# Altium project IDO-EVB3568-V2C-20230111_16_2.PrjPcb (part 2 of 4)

## Sheet P07.SchDoc
size 594 x 420 mm
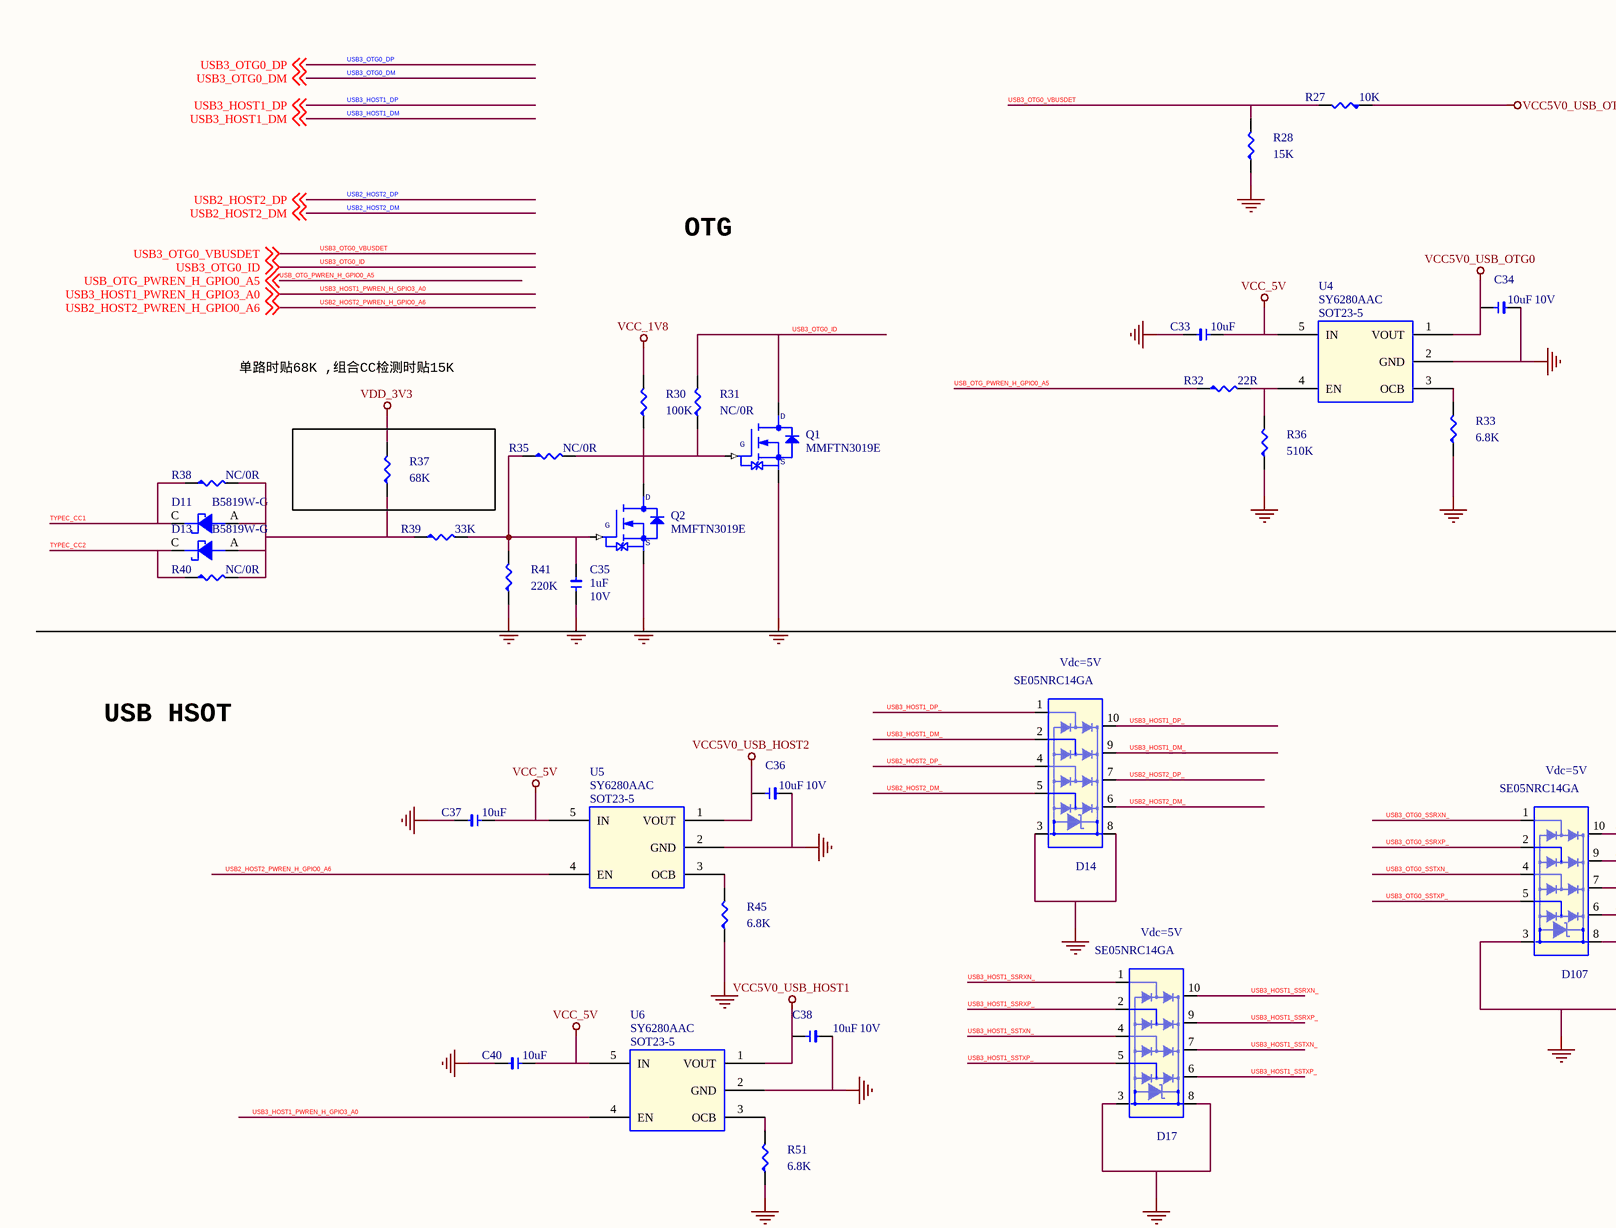
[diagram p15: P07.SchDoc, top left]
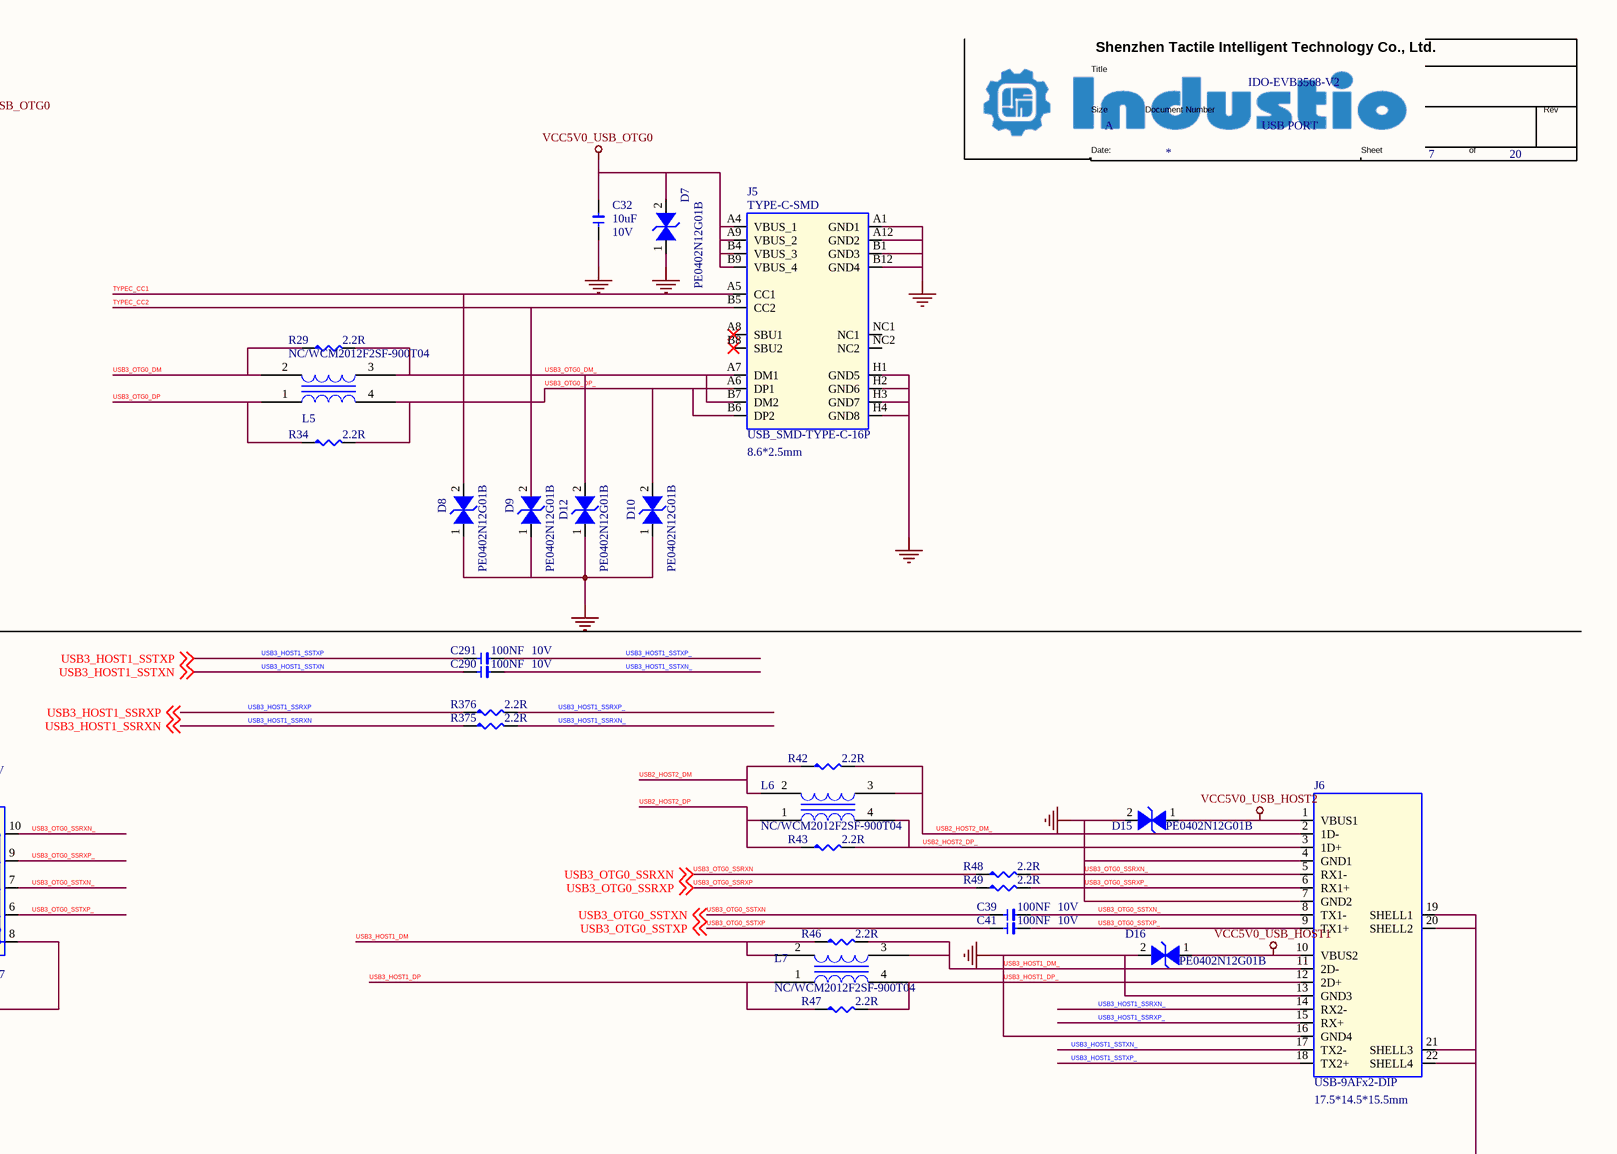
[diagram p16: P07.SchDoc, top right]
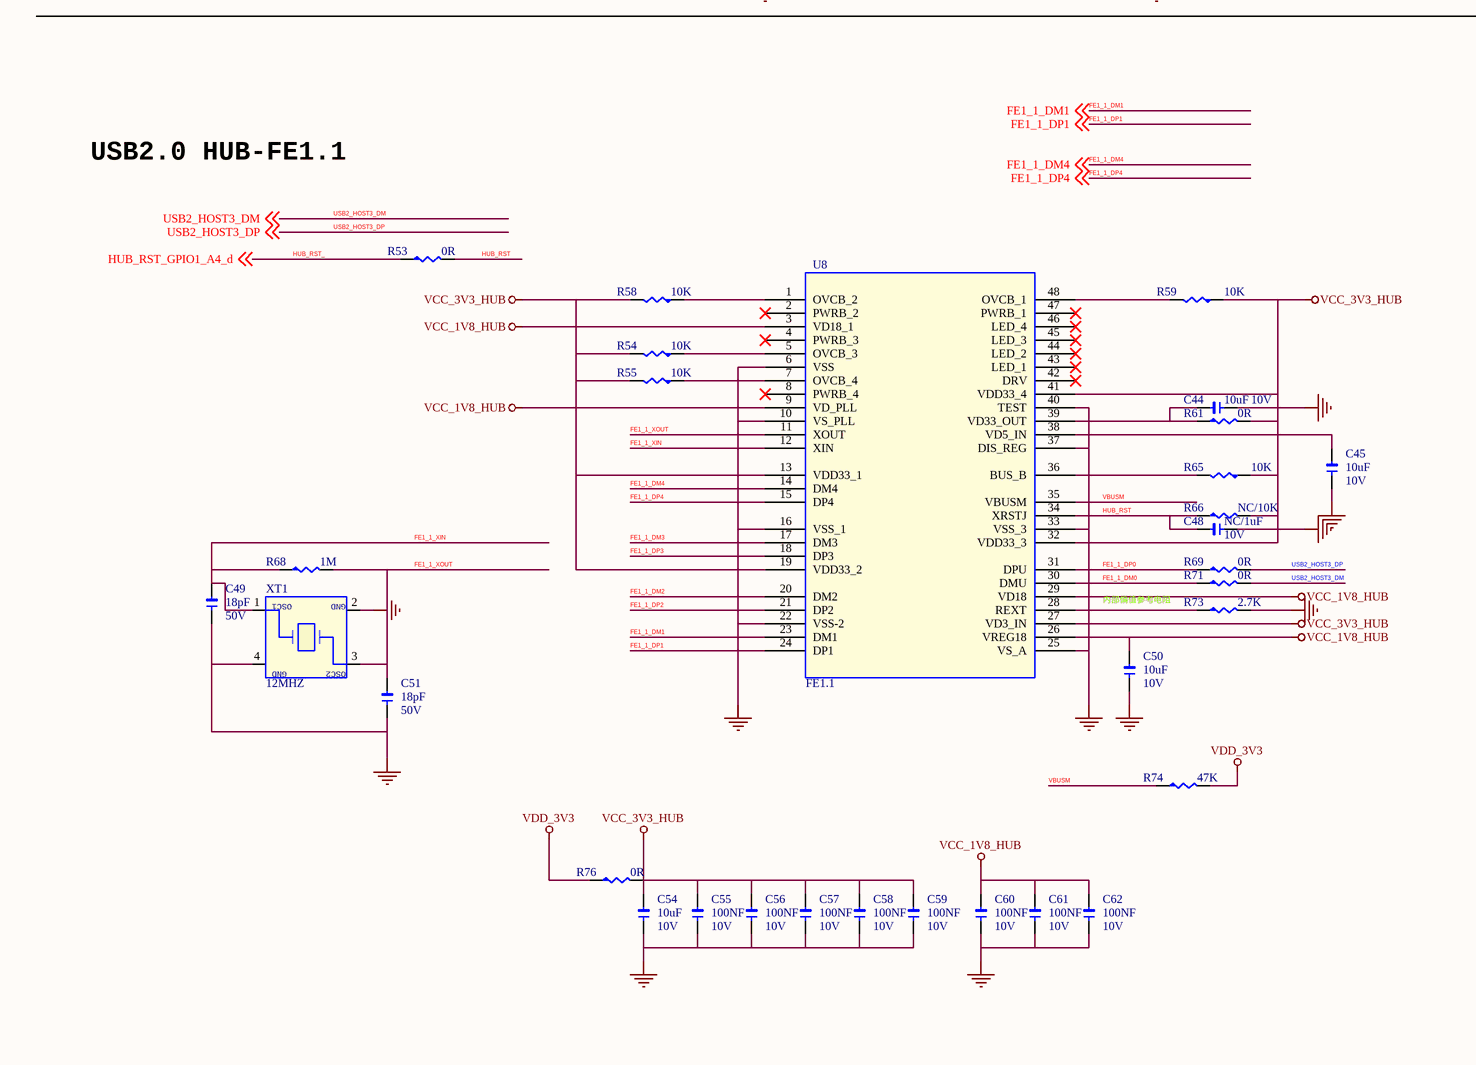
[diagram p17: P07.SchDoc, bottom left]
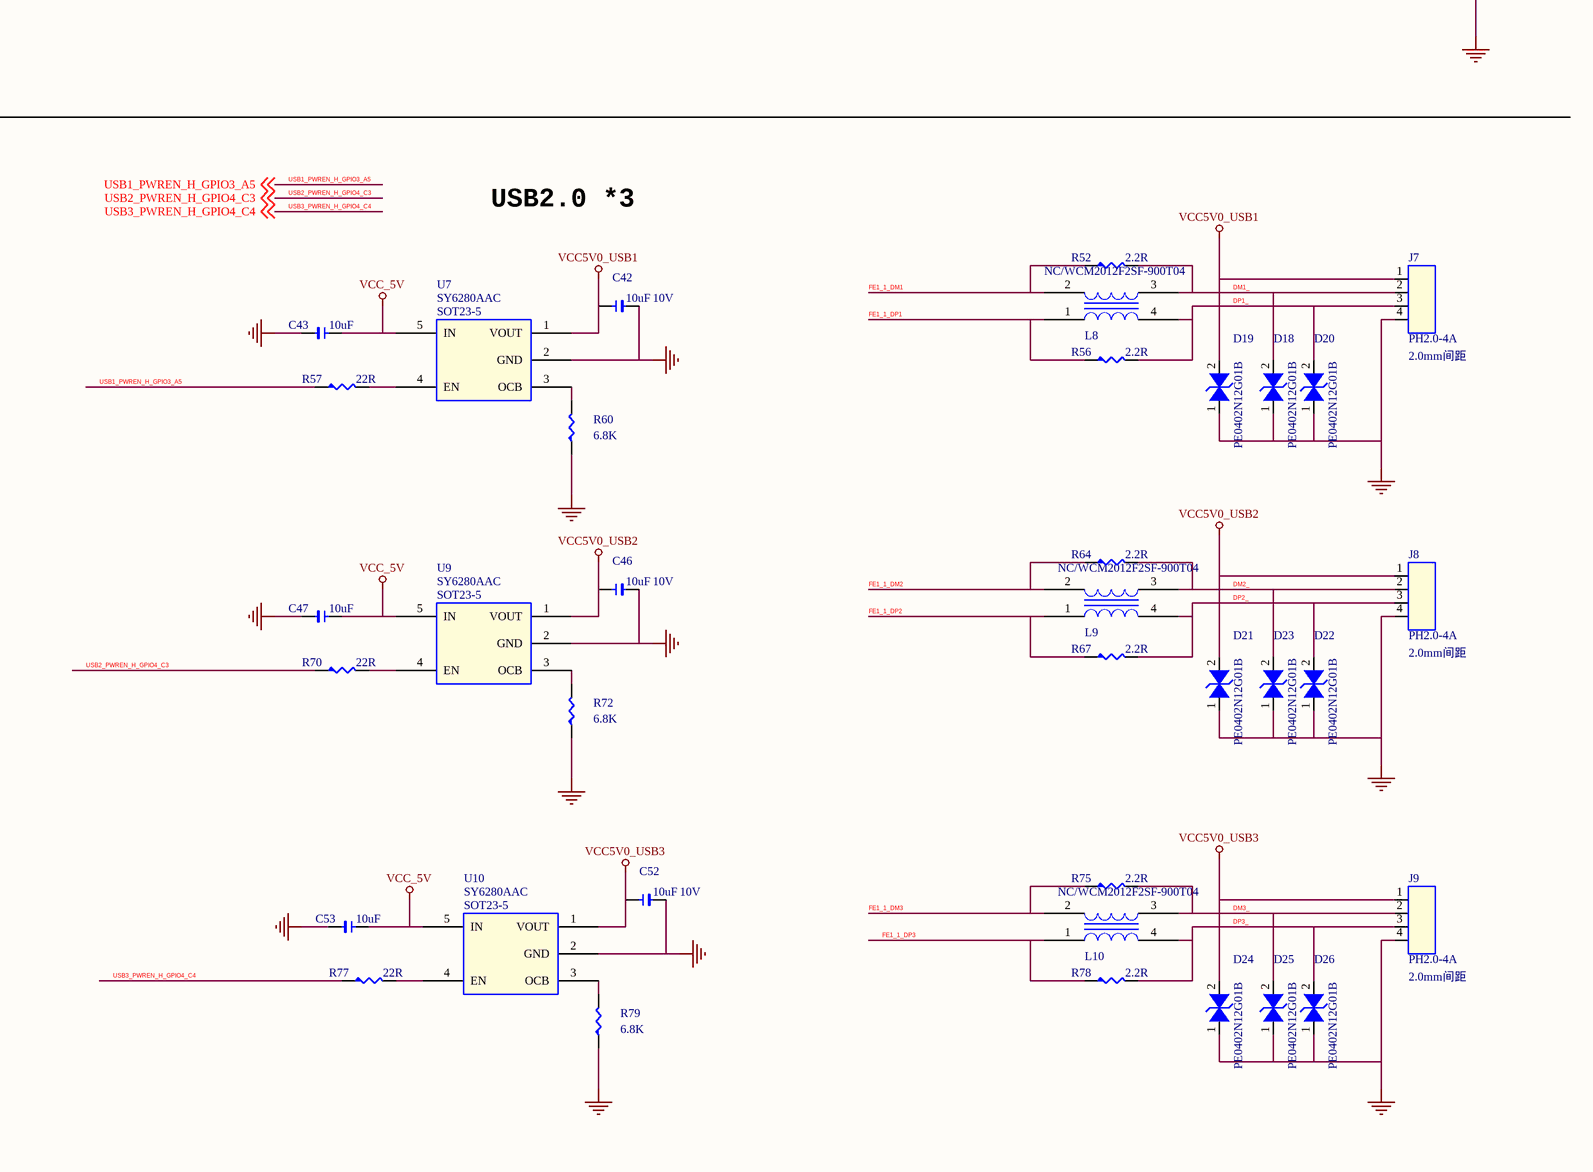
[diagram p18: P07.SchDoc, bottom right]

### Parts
(Parts that share a designator on the sheet are numbered #1, #2 ... from top to bottom, then left to right.)
*#6  Doc: USB PORT  Title: IDO-EVB3568-V2  Page Size: A  Page Number: 7  Page Count: 20  (hidden comment: TitleBlock1)  (graphical)
C32  10uF  DSC2: 10V  [1206]
C33  10uF  [1206]
C34  10uF  DSC2: 10V  [1206]
C35  1uF  DSC2: 10V  [1206]
C36  10uF  DSC2: 10V  [1206]
C37  10uF  [1206]
C38  10uF  DSC2: 10V  [1206]
C39  100NF  DSC2: 10V  [1206]
C40  10uF  [1206]
C41  100NF  DSC2: 10V  [1206]
C42  10uF  DSC2: 10V  [1206]
C43  10uF  [1206]
C44  10uF  DSC2: 10V  [1206]
C45  10uF  DSC2: 10V  [1206]
C46  10uF  DSC2: 10V  [1206]
C47  10uF  [1206]
C48  NC/1uF  DSC2: 10V  [1206]
C49  18pF  DSC2: 50V  [1206]
C50  10uF  DSC2: 10V  [1206]
C51  18pF  DSC2: 50V  [1206]
C52  10uF  DSC2: 10V  [1206]
C53  10uF  [1206]
C54  10uF  DSC2: 10V  [1206]
C55  100NF  DSC2: 10V  [1206]
C56  100NF  DSC2: 10V  [1206]
C57  100NF  DSC2: 10V  [1206]
C58  100NF  DSC2: 10V  [1206]
C59  100NF  DSC2: 10V  [1206]
C60  100NF  DSC2: 10V  [1206]
C61  100NF  DSC2: 10V  [1206]
C62  100NF  DSC2: 10V  [1206]
C290  100NF  DSC2: 10V  [1206]
C291  100NF  DSC2: 10V  [1206]
D7  PE0402N12G01B  [V0402]
D8  PE0402N12G01B  [V0402]
D9  PE0402N12G01B  [V0402]
D10  PE0402N12G01B  [V0402]
D11  B5819W-G  [SOD123]
D12  PE0402N12G01B  [V0402]
D13  B5819W-G  [SOD123]
D14  SE05NRC14GA  DSC2: Vdc=5V  [DFN2510-10L]
D15  PE0402N12G01B  [V0402]
D16  PE0402N12G01B  [V0402]
D17  SE05NRC14GA  DSC2: Vdc=5V  [DFN2510-10L]
D18  PE0402N12G01B  [V0402]
D19  PE0402N12G01B  [V0402]
D20  PE0402N12G01B  [V0402]
D21  PE0402N12G01B  [V0402]
D22  PE0402N12G01B  [V0402]
D23  PE0402N12G01B  [V0402]
D24  PE0402N12G01B  [V0402]
D25  PE0402N12G01B  [V0402]
D26  PE0402N12G01B  [V0402]
D107  SE05NRC14GA  DSC2: Vdc=5V  [DFN2510-10L]
J5  TYPE-C-SMD  DSC2: 8.6*2.5mm  [USB_SMD-TYPE-C-16P]
J6  USB-9AFx2-DIP  DSC2: 17.5*14.5*15.5mm  [USB-9AF-DIP_2x]
J7  PH2.0-4A  DSC2: 2.0mm间距  [PH200-4A]
J8  PH2.0-4A  DSC2: 2.0mm间距  [PH200-4A]
J9  PH2.0-4A  DSC2: 2.0mm间距  [PH200-4A]
L5  NC/WCM2012F2SF-900T04  [CMLS-ACM2012]
L6  NC/WCM2012F2SF-900T04  [CMLS-ACM2012]
L7  NC/WCM2012F2SF-900T04  [CMLS-ACM2012]
L8  NC/WCM2012F2SF-900T04  [CMLS-ACM2012]
L9  NC/WCM2012F2SF-900T04  [CMLS-ACM2012]
L10  NC/WCM2012F2SF-900T04  [CMLS-ACM2012]
Q1  MMFTN3019E  [SOT523]
Q2  MMFTN3019E  [SOT523]
R27  10K  [R0402]
R28  15K  [R0402]
R29  2.2R  [R0402]
R30  100K  [R0402]
R31  NC/0R  [R0402]
R32  22R  [R0402]
R33  6.8K  [R0402]
R34  2.2R  [R0402]
R35  NC/0R  [R0402]
R36  510K  [R0402]
R37  68K  [R0402]
R38  NC/0R  [R0402]
R39  33K  [R0402]
R40  NC/0R  [R0402]
R41  220K  [R0402]
R42  2.2R  [R0402]
R43  2.2R  [R0402]
R45  6.8K  [R0402]
R46  2.2R  [R0402]
R47  2.2R  [R0402]
R48  2.2R  [R0402]
R49  2.2R  [R0402]
R51  6.8K  [R0402]
R52  2.2R  [R0402]
R53  0R  [R0402]
R54  10K  [R0402]
R55  10K  [R0402]
R56  2.2R  [R0402]
R57  22R  [R0402]
R58  10K  [R0402]
R59  10K  [R0402]
R60  6.8K  [R0402]
R61  0R  [R0402]
R64  2.2R  [R0402]
R65  10K  [R0402]
R66  NC/10K  [R0402]
R67  2.2R  [R0402]
R68  1M  [R0402]
R69  0R  [R0402]
R70  22R  [R0402]
R71  0R  [R0402]
R72  6.8K  [R0402]
R73  2.7K  [R0402]
R74  47K  [R0402]
R75  2.2R  [R0402]
R76  0R  [R0402]
R77  22R  [R0402]
R78  2.2R  [R0402]
R79  6.8K  [R0402]
R375  2.2R  [R0402]
R376  2.2R  [R0402]
U4  SY6280AAC  [SOT23-5]
U5  SY6280AAC  [SOT23-5]
U6  SY6280AAC  [SOT23-5]
U7  SY6280AAC  [SOT23-5]
U8  FE1.1  [LQFP-48_7x7x05P]
U9  SY6280AAC  [SOT23-5]
U10  SY6280AAC  [SOT23-5]
XT1  12MHZ  [xtal_32x25_4p]

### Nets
GND: C32.1 C33.2 C34.2 C35.1 C36.2 C37.2 C38.2 C40.2 C42.2 C43.2 C44.1 C45.1 C46.2 C47.2 C48.1 C49.1 C50.1 C51.1 C52.2 C53.2 C54.1 C55.1 C56.1 C57.1 C58.1 C59.1 C60.1 C61.1 C62.1 D7.1(I/O2) D8.1(I/O2) D9.1(I/O2) D10.1(I/O2) D12.1(I/O2) D14.1 D14.2 D14.3 D14.8 D14.9 D14.10 D15.2(I/O1) D16.2(I/O1) D17.3 D17.8 D18.1(I/O2) D19.1(I/O2) D20.1(I/O2) D21.1(I/O2) D22.1(I/O2) D23.1(I/O2) D24.1(I/O2) D25.1(I/O2) D26.1(I/O2) D107.1 D107.2 D107.3 D107.8 D107.9 D107.10 J5.A1(GND1) J5.A12(GND2) J5.B1(GND3) J5.B12(GND4) J5.H1(GND5) J5.H2(GND6) J5.H3(GND7) J5.H4(GND8) J6.4(GND1) J6.5(RX1-) J6.6(RX1+) J6.7(GND2) J6.11(2D-) J6.12(2D+) J6.13(GND3) J6.16(GND4) J6.19(SHELL1) J6.20(SHELL2) J6.21(SHELL3) J6.22(SHELL4) J7.4 J8.4 J9.4 L7.3 L7.4 Q1.2(SOURCE) Q2.2(SOURCE) R28.1 R33.1 R36.1 R41.1 R45.1 R46.2 R47.2 R48.2 R49.2 R51.1 R60.1 R72.1 R73.2 R79.1 U4.2(GND) U5.2(GND) U6.2(GND) U7.2(GND) U8.6(VSS) U8.10(VS_PLL) U8.16(VSS_1) U8.22(VSS-2) U8.25(VS_A) U8.33(VSS_3) U8.37(DIS_REG) U8.40(TEST) U9.2(GND) U10.2(GND) XT1.2 XT1.4  [also labelled USB3_HOST1_DM_, USB3_HOST1_DP_, USB3_OTG0_SSRXN_, USB3_OTG0_SSRXP_]  [project net EDP_TX_AUXP_]
VCC5V0_USB1: C42.1 D19.2(I/O1) J7.1 U7.1(VOUT)
VCC5V0_USB2: C46.1 D21.2(I/O1) J8.1 U9.1(VOUT)
VCC5V0_USB3: C52.1 D24.2(I/O1) J9.1 U10.1(VOUT)
VCC5V0_USB_HOST1: C38.1 D16.1(I/O2) J6.10(VBUS2) U6.1(VOUT)
VCC5V0_USB_HOST2: C36.1 D15.1(I/O2) J6.1(VBUS1) U5.1(VOUT)
VCC5V0_USB_OTG0: C32.2 C34.1 D7.2(I/O1) J5.A4(VBUS_1) J5.A9(VBUS_2) J5.B4(VBUS_3) J5.B9(VBUS_4) R27.1 U4.1(VOUT)
VCC_1V8: R30.2
VCC_1V8_HUB: C50.2 C60.2 C61.2 C62.2 U8.3(VD18_1) U8.9(VD_PLL) U8.26(VREG18) U8.29(VD18)
VCC_3V3_HUB: C54.2 C55.2 C56.2 C57.2 C58.2 C59.2 R54.2 R55.2 R58.2 R59.1 R61.2 R65.1 R66.2 R76.2 U8.13(VDD33_1) U8.19(VDD33_2) U8.27(VD3_IN) U8.32(VDD33_3) U8.41(VDD33_4)
VCC_5V: C33.1 C37.1 C40.1 C43.1 C47.1 C53.1 U4.5(IN) U5.5(IN) U6.5(IN) U7.5(IN) U9.5(IN) U10.5(IN)
VDD_3V3: R37.2 R74.2 R76.1
DM1_: D18.2(I/O1) J7.2 L8.3 R52.2
DM2_: D23.2(I/O1) J8.2 L9.3 R64.2
DM3_: D25.2(I/O1) J9.2 L10.3 R75.2
DP1_: D20.2(I/O1) J7.3 L8.4 R56.2
DP2_: D22.2(I/O1) J8.3 L9.4 R67.2
DP3_: D26.2(I/O1) J9.3 L10.4 R78.2
FE1_1_DM0: R71.1 U8.30(DMU)
FE1_1_DM1: L8.2 R52.1 U8.23(DM1) ; off-sheet FE1_1_DM1
FE1_1_DM2: L9.2 R64.1 U8.20(DM2)
FE1_1_DM3: L10.2 R75.1 U8.17(DM3)
FE1_1_DM4: U8.14(DM4) ; off-sheet FE1_1_DM4
FE1_1_DP0: R69.1 U8.31(DPU)
FE1_1_DP1: L8.1 R56.1 U8.24(DP1) ; off-sheet FE1_1_DP1
FE1_1_DP2: L9.1 R67.1 U8.21(DP2)
FE1_1_DP3: L10.1 R78.1 U8.18(DP3)
FE1_1_DP4: U8.15(DP4) ; off-sheet FE1_1_DP4
FE1_1_XIN: C49.2 R68.1 U8.12(XIN) XT1.1
FE1_1_XOUT: C51.2 R68.2 U8.11(XOUT) XT1.3
HUB_RST: C48.2 R53.2 R66.1 U8.34(XRSTJ)
HUB_RST_: R53.1 ; off-sheet HUB_RST_GPIO1_A4_d  [also labelled HUB_RST_GPIO1_A4_d]
TYPEC_CC1: D8.2(I/O1) D11.C J5.A5(CC1) R38.1
TYPEC_CC2: D9.2(I/O1) D13.C J5.B5(CC2) R40.1
USB1_PWREN_H_GPIO3_A5: R57.1 ; off-sheet USB1_PWREN_H_GPIO3_A5
USB2_HOST2_DM: L6.2 R42.1 ; off-sheet USB2_HOST2_DM
USB2_HOST2_DM_: D14.5 D14.6 J6.2(1D-) L6.3 R42.2
USB2_HOST2_DP: L6.1 R43.1 ; off-sheet USB2_HOST2_DP
USB2_HOST2_DP_: D14.4 D14.7 J6.3(1D+) L6.4 R43.2
USB2_HOST2_PWREN_H_GPIO0_A6: U5.4(EN) ; off-sheet USB2_HOST2_PWREN_H_GPIO0_A6
USB2_HOST3_DM: R71.2 ; off-sheet USB2_HOST3_DM
USB2_HOST3_DP: R69.2 ; off-sheet USB2_HOST3_DP
USB2_PWREN_H_GPIO4_C3: R70.1 ; off-sheet USB2_PWREN_H_GPIO4_C3
USB3_HOST1_DM: L7.2 R46.1 ; off-sheet USB3_HOST1_DM
USB3_HOST1_DP: L7.1 R47.1 ; off-sheet USB3_HOST1_DP
USB3_HOST1_PWREN_H_GPIO3_A0: U6.4(EN) ; off-sheet USB3_HOST1_PWREN_H_GPIO3_A0
USB3_HOST1_SSRXN: R375.1 ; off-sheet USB3_HOST1_SSRXN
USB3_HOST1_SSRXN_: D17.1 D17.10 J6.14(RX2-) R375.2
USB3_HOST1_SSRXP: R376.1 ; off-sheet USB3_HOST1_SSRXP
USB3_HOST1_SSRXP_: D17.2 D17.9 J6.15(RX+) R376.2
USB3_HOST1_SSTXN: C290.1 ; off-sheet USB3_HOST1_SSTXN
USB3_HOST1_SSTXN_: C290.2 D17.4 D17.7 J6.17(TX2-)
USB3_HOST1_SSTXP: C291.1 ; off-sheet USB3_HOST1_SSTXP
USB3_HOST1_SSTXP_: C291.2 D17.5 D17.6 J6.18(TX2+)
USB3_OTG0_DM: L5.2 R29.1 ; off-sheet USB3_OTG0_DM
USB3_OTG0_DM_: D12.2(I/O1) J5.A7(DM1) J5.B7(DM2) L5.3 R29.2
USB3_OTG0_DP: L5.1 R34.1 ; off-sheet USB3_OTG0_DP
USB3_OTG0_DP_: D10.2(I/O1) J5.A6(DP1) J5.B6(DP2) L5.4 R34.2
USB3_OTG0_ID: Q1.3(DRAIN) R31.2 ; off-sheet USB3_OTG0_ID
USB3_OTG0_SSRXN: R48.1 ; off-sheet USB3_OTG0_SSRXN
USB3_OTG0_SSRXP: R49.1 ; off-sheet USB3_OTG0_SSRXP
USB3_OTG0_SSTXN: C39.1 ; off-sheet USB3_OTG0_SSTXN
USB3_OTG0_SSTXN_: C39.2 D107.4 D107.7 J6.8(TX1-)
USB3_OTG0_SSTXP: C41.1 ; off-sheet USB3_OTG0_SSTXP
USB3_OTG0_SSTXP_: C41.2 D107.5 D107.6 J6.9(TX1+)
USB3_OTG0_VBUSDET: R27.2 R28.2 ; off-sheet USB3_OTG0_VBUSDET
USB3_PWREN_H_GPIO4_C4: R77.1 ; off-sheet USB3_PWREN_H_GPIO4_C4
USB_OTG_PWREN_H_GPIO0_A5: R32.1 ; off-sheet USB_OTG_PWREN_H_GPIO0_A5
VBUSM: R74.1 U8.35(VBUSM)
NetC35_2: C35.2 Q2.1(GATE) R35.1 R39.2 R41.2
NetC44_2: C44.2 R61.1 U8.39(VD33_OUT)
NetC45_2: C45.2 U8.38(VD5_IN)
NetD11_A: D11.A D13.A R37.1 R38.2 R39.1 R40.2
NetQ1_1: Q1.1(GATE) Q2.3(DRAIN) R30.1 R31.1 R35.2
NetR32_2: R32.2 R36.2 U4.4(EN)
NetR33_2: R33.2 U4.3(OCB)
NetR45_2: R45.2 U5.3(OCB)
NetR51_2: R51.2 U6.3(OCB)
NetR54_1: R54.1 U8.5(OVCB_3)
NetR55_1: R55.1 U8.7(OVCB_4)
NetR57_2: R57.2 U7.4(EN)
NetR58_1: R58.1 U8.1(OVCB_2)
NetR59_2: R59.2 U8.48(OVCB_1)
NetR60_2: R60.2 U7.3(OCB)
NetR65_2: R65.2 U8.36(BUS_B)
NetR70_2: R70.2 U9.4(EN)
NetR72_2: R72.2 U9.3(OCB)
NetR73_1: R73.1 U8.28(REXT)
NetR77_2: R77.2 U10.4(EN)
NetR79_2: R79.2 U10.3(OCB)

Not connected (* = marked no-connect by the designer): J5 A8(SBU1)* B8(SBU2)* NC1 NC2; U8 2(PWRB_2)* 4(PWRB_3)* 8(PWRB_4)* 42(DRV)* 43(LED_1)* 44(LED_2)* 45(LED_3)* 46(LED_4)* 47(PWRB_1)*

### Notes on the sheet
- OTG
- 单路时贴68K ,组合CC检测时贴15K
- USB HSOT
- USB2.0 *3
- USB2.0 HUB-FE1.1
- 内部偏值参考电阻

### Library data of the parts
C32 C42 C46 C52 = C-0603_Dup1: Part Number: C020102120071; Part Name: 贴片电容; Manufacture: 三星¦国巨¦村田; PCB Footprint: C0603; ERP Number: 1010200076; DSC1: ±20%; DSC3: X5R; ID: 71
C33 C37 C40 = C-0603: Part Number: C020102120071; Part Name: 贴片电容; Manufacture: 三星¦国巨¦村田; PCB Footprint: C0603; ERP Number: 1010200076; DSC1: ±20%; DSC2: 10V; DSC3: X5R; ID: 71
C34 C36 C38 = C-0603_Dup1: Manufacture: 三星¦国巨¦村田; Part Name: 贴片电容; Part Number: C020102120071; PCB Footprint: C0603; ID: 71; DSC3: X5R; DSC1: ±20%; ERP Number: 1010200076
C35 = C-0402_Dup2: Manufacture: 三星¦国巨¦村田; Part Name: 贴片电容; Part Number: C020102120064; ID: 64; DSC3: X5R; DSC1: ±10%; ERP Number: 1010200054; PCB Footprint: C0402
C39 C41 C60-C62 = C-0402_Dup2: Part Number: C020102120060; Part Name: 贴片电容; Manufacture: 三星¦国巨¦村田; PCB Footprint: C0402; DSC1: ±10%; DSC3: X7R; ID: 60
C43 C47 C53 = C-0603: Manufacture: 三星¦国巨¦村田; Part Name: 贴片电容; Part Number: C020102120071; PCB Footprint: C0603; ID: 71; DSC3: X5R; DSC2: 10V; DSC1: ±20%; ERP Number: 1010200076
C44 C45 C54 = C-0603_Dup2: Part Number: C020102120071; Part Name: 贴片电容; Manufacture: 三星¦国巨¦村田; PCB Footprint: C0603; ERP Number: 1010200076; DSC1: ±20%; DSC3: X5R; ID: 71
C48 = C-0402_Dup2: Manufacture: 三星¦国巨¦村田; Part Name: 贴片电容; Part Number: C020102120064; PCB Footprint: C0402; ID: 64; DSC3: X5R; DSC1: ±10%; ERP Number: 1010200054
C49 C51 = C-0402_Dup2: Part Number: C020102120027; Part Name: 贴片电容; Manufacture: 三星¦国巨¦村田; PCB Footprint: C0402; ERP Number: 1010200091; DSC1: ±5%; DSC3: C0G; ID: 27
C50 = C-0603_Dup2: Manufacture: 三星¦国巨¦村田; Part Name: 贴片电容; Part Number: C020102120071; PCB Footprint: C0603; ID: 71; DSC3: X5R; DSC1: ±20%; ERP Number: 1010200076
C55-C59 = C-0402_Dup2: Manufacture: 三星¦国巨¦村田; Part Name: 贴片电容; Part Number: C020102120060; PCB Footprint: C0402; ID: 60; DSC3: X7R; DSC1: ±10%
C290 C291 = C-0402_Dup1: Manufacture: 三星¦国巨¦村田; Part Name: 贴片电容; Part Number: C020102120060; PCB Footprint: C0402; ID: 60; DSC3: X7R; DSC1: ±10%
D7-D9 D15 D16 D19 D21 D24 = DI-ESD: ESD 0402; Manufacturer: INPAQ; Manufacture P/N: MLVG04021R0UV18; Part Number: C040504013980; Manufacture: 硕凯; PN Type: Varistor; DSC1: 双向; DSC2: Vdc=12V; DSC4: Vc=40V; DSC5: Cj=0.05pF; ID: 1; Solder: 推荐
D10 D12 D18 D20 D22 D23 D25 D26 = DI-ESD: ESD 0402; Manufacturer: INPAQ; Manufacture P/N: MLVG04021R0UV18; Part Number: C040504013980; Manufacture: 硕凯; PN Type: Varistor; Solder: 推荐; ID: 1; DSC5: Cj=0.05pF; DSC4: Vc=40V; DSC2: Vdc=12V; DSC1: 双向
D11 D13 = DI-XI-S_Dup1: Part Number: C040202220005; Part Name: 肖特基二级管; Manufacture: 长电; CLASS: IC; DSC1: VR=40V; DSC2: IF=1A; DSC3: VF=600mV/1A; DSC4: IR=1mA; ID: 5
D14 = DI-ESD-SE05NRC14GA: Part Name: ESD; Part Number: C040504013981; Manufacture: 硕凯; DSC1: 双向; DSC3: Vbr=8V; DSC4: Vc=20V; DSC5: Cj=0.4pF; ID: 8; Solder: 推荐
D17 D107 = DI-ESD-SE05NRC14GA: Manufacture: 硕凯; Part Number: C040504013981; Part Name: ESD; Solder: 推荐; ID: 8; DSC5: Cj=0.4pF; DSC4: Vc=20V; DSC3: Vbr=8V; DSC1: 双向
J5 = J-TYPE_C_16P: Part Name: USB连接器; Part Number: J060111203952; ID: 11; DSC5: TYPE-CF-16P-RAT-L7.3（九龙熹）; DSC4: U262-161N-4BVC11（星坤）; DSC3: 卧贴; DSC1: TYPE-C，16Pin母座，卧贴，无卷边，耐高温
J6 = J-USB-9AFx2-DIP-W: USB,TYPE-A,2PORT,R/A,W/SHIELD; Part Name: USB连接器; Part Number: J060111093946; VSTNO: H00025; ID: 14; DSC5: JLX-USB-030（九龙熹）; DSC3: 通孔弯针; DSC1: USB-3.0，插件弯脚，双层，蓝胶，有卷边，耐高温
J7 J8 = J-H-4P: Part Number: J020302820003; Part Name: PH; DSC1: 4p; DSC3: 通孔180度直针; DSC4: 米黄色胶壳 耐高温; DSC5: JLX-PH20-4A（九龙熹）; DSC6: X2016WV-04-46SN(星坤); ID: 13
J9 = J-H-4P: Part Name: PH; Part Number: J020302820003; ID: 13; DSC6: X2016WV-04-46SN(星坤); DSC5: JLX-PH20-4A（九龙熹）; DSC4: 米黄色胶壳 耐高温; DSC3: 通孔180度直针; DSC1: 4p
L5 = L-CMLS-ACM2012: Part Name: 信号共模电感; Part Number: C060402360001; Manufacture: 台庆; ERP Number: 1010200196; DSC1: 90uH@100kHz; DSC2: 90Ω@100MHz; DSC3: 400mA; DSC4: DCR=300mΩ; DSC5: -40℃ ~ +125℃; DSC6: SMD_4P,2x1.2mm; ID: 1
L6 = L-CMLS-ACM2012_Dup1: Manufacture: 台庆; Part Number: C060402360001; Part Name: 信号共模电感; ID: 1; DSC6: SMD_4P,2x1.2mm; DSC5: -40℃ ~ +125℃; DSC4: DCR=300mΩ; DSC3: 400mA; DSC2: 90Ω@100MHz; DSC1: 90uH@100kHz; ERP Number: 1010200196
L7 = L-CMLS-ACM2012_Dup1: Part Name: 信号共模电感; Part Number: C060402360001; Manufacture: 台庆; ERP Number: 1010200196; DSC1: 90uH@100kHz; DSC2: 90Ω@100MHz; DSC3: 400mA; DSC4: DCR=300mΩ; DSC5: -40℃ ~ +125℃; DSC6: SMD_4P,2x1.2mm; ID: 1
L8-L10 = L-CMLS-ACM2012: Manufacture: 台庆; Part Number: C060402360001; Part Name: 信号共模电感; ID: 1; DSC6: SMD_4P,2x1.2mm; DSC5: -40℃ ~ +125℃; DSC4: DCR=300mΩ; DSC3: 400mA; DSC2: 90Ω@100MHz; DSC1: 90uH@100kHz; ERP Number: 1010200196
Q1 Q2 = N-MOS-Q_Dup1: Manufacture: 先科; Part Name: N-MOS; Part Number: C030202190004; ID: 4; DSC5: pd=150mW; DSC4: Vgs=±20V; DSC3: Vgs(th)=1.5V; DSC2: Id=100mA; DSC1: Vds=30V; ERP Number: 1010800011
R27 R54 R55 R59 = R-0402_Dup4: Part Name: 贴片电阻; Part Number: C011002080328; ERP Number: 1010200096; DSC1: ±5%; DSC2: 1/16W; ID: 328
R28 = R-0402_Dup4: Part Name: 贴片电阻; Part Number: C011002080332; ERP Number: 1010200258; DSC1: ±5%; DSC2: 1/16W; ID: 332
R29 R42 R47 R48 R56 R67 R78 R375 = R-0402_Dup4: Part Number: C011002080238; Part Name: 贴片电阻; ID: 238; DSC2: 1/16W; DSC1: ±5%; ERP Number: 1010200263
R30 = R-0402_Dup4: Part Name: 贴片电阻; Part Number: C011002080353; ERP Number: 1010200103; DSC1: ±5%; DSC2: 1/16W; ID: 353
R31 R35 R38 R40 R53 R61 R69 R71 R76 = R-0402_Dup4: Part Number: C011002080217; Part Name: 贴片电阻; ID: 217; DSC2: 1/16W; DSC1: ±5%; ERP Number: 1010200100
R32 R57 R70 R77 = R-0402_Dup4: Part Number: C011002080262; Part Name: 贴片电阻; ID: 262; DSC2: 1/16W; DSC1: ±5%; ERP Number: 1010200173
R33 R51 R60 R72 R79 = R-0402_Dup4: Part Name: 贴片电阻; Part Number: C011002080324; DSC1: ±5%; DSC2: 1/16W; ID: 324
R34 R43 R46 R49 R52 R64 R75 R376 = R-0402_Dup4: Part Name: 贴片电阻; Part Number: C011002080238; ERP Number: 1010200263; DSC1: ±5%; DSC2: 1/16W; ID: 238
R36 = R-0402_Dup4: Part Name: 贴片电阻; Part Number: C011002080371; DSC1: ±5%; DSC2: 1/16W; ID: 371
R37 = R-0402_Dup4: Part Name: 贴片电阻; Part Number: C011002080349; DSC1: ±5%; DSC2: 1/16W; ID: 349
R39 = R-0402_Dup4: Part Name: 贴片电阻; Part Number: C011002080341; ERP Number: 1010200469; DSC1: ±5%; DSC2: 1/16W; ID: 341
R41 = R-0402_Dup4: Part Name: 贴片电阻; Part Number: C011002080362; DSC1: ±5%; DSC2: 1/16W; ID: 362
R45 = R-0402_Dup4: Part Number: C011002080324; Part Name: 贴片电阻; ID: 324; DSC2: 1/16W; DSC1: ±5%
R58 R65 = R-0402_Dup4: Part Number: C011002080328; Part Name: 贴片电阻; ID: 328; DSC2: 1/16W; DSC1: ±5%; ERP Number: 1010200096
R66 = R-0402_Dup5: Part Number: C011002080856; Part Name: 贴片电阻; ID: 856; DSC2: 1/16W; DSC1: ±1%; ERP Number: 1010200140
R68 = R-0402_Dup4: Part Name: 贴片电阻; Part Number: C011002080378; ERP Number: 1010200167; DSC1: ±5%; DSC2: 1/16W; ID: 378
R73 = R-0402_Dup5: Part Name: 贴片电阻; Part Number: C011002080789; DSC1: ±1%; DSC2: 1/16W; ID: 789
R74 = R-0402_Dup4: Part Number: C011002080345; Part Name: 贴片电阻; ID: 345; DSC2: 1/16W; DSC1: ±5%; ERP Number: 1010200182
U4-U6 = U-SY6280AAC_1: Part Number: C070402430001; Part Name: 功率开关; Manufacture: 矽力杰; ERP Number: 1010100222; DSC1: 低能耗电源开关; DSC2: 2.4-5.5V 2A; DSC3: 80m?; DSC4: -40~85℃; ID: 1
U7 U9 U10 = U-SY6280AAC_1: Manufacture: 矽力杰; Part Name: 功率开关; Part Number: C070402430001; ID: 1; DSC4: -40~85℃; DSC3: 80m?; DSC2: 2.4-5.5V 2A; DSC1: 低能耗电源开关; ERP Number: 1010100222
U8 = U-FE2_0.1: Part Number: C100202500010; Part Name: USB芯片; Manufacture: TERMINUS; DSC1: USB 2.0 HIGH SPEED 7-PORT HUB CONTROLLER; DSC2: 48 PIN LQFP - 7mmX7mm,0.5 Pitch; ID: 21
XT1 = XTAL-4P_Dup1: Manufacture: 泰晶; Part Number: C050102290004; Part Name: 贴片无源晶振; CLASS: IC; ID: 4; DSC5: 3.2*2.5mm 4P; DSC4: -40℃~+85℃; DSC3: 12pF; DSC2: ±10ppm; DSC1: 100Ω; ERP Number: 1010700002

## Sheet P08.SchDoc
size 420 x 297 mm
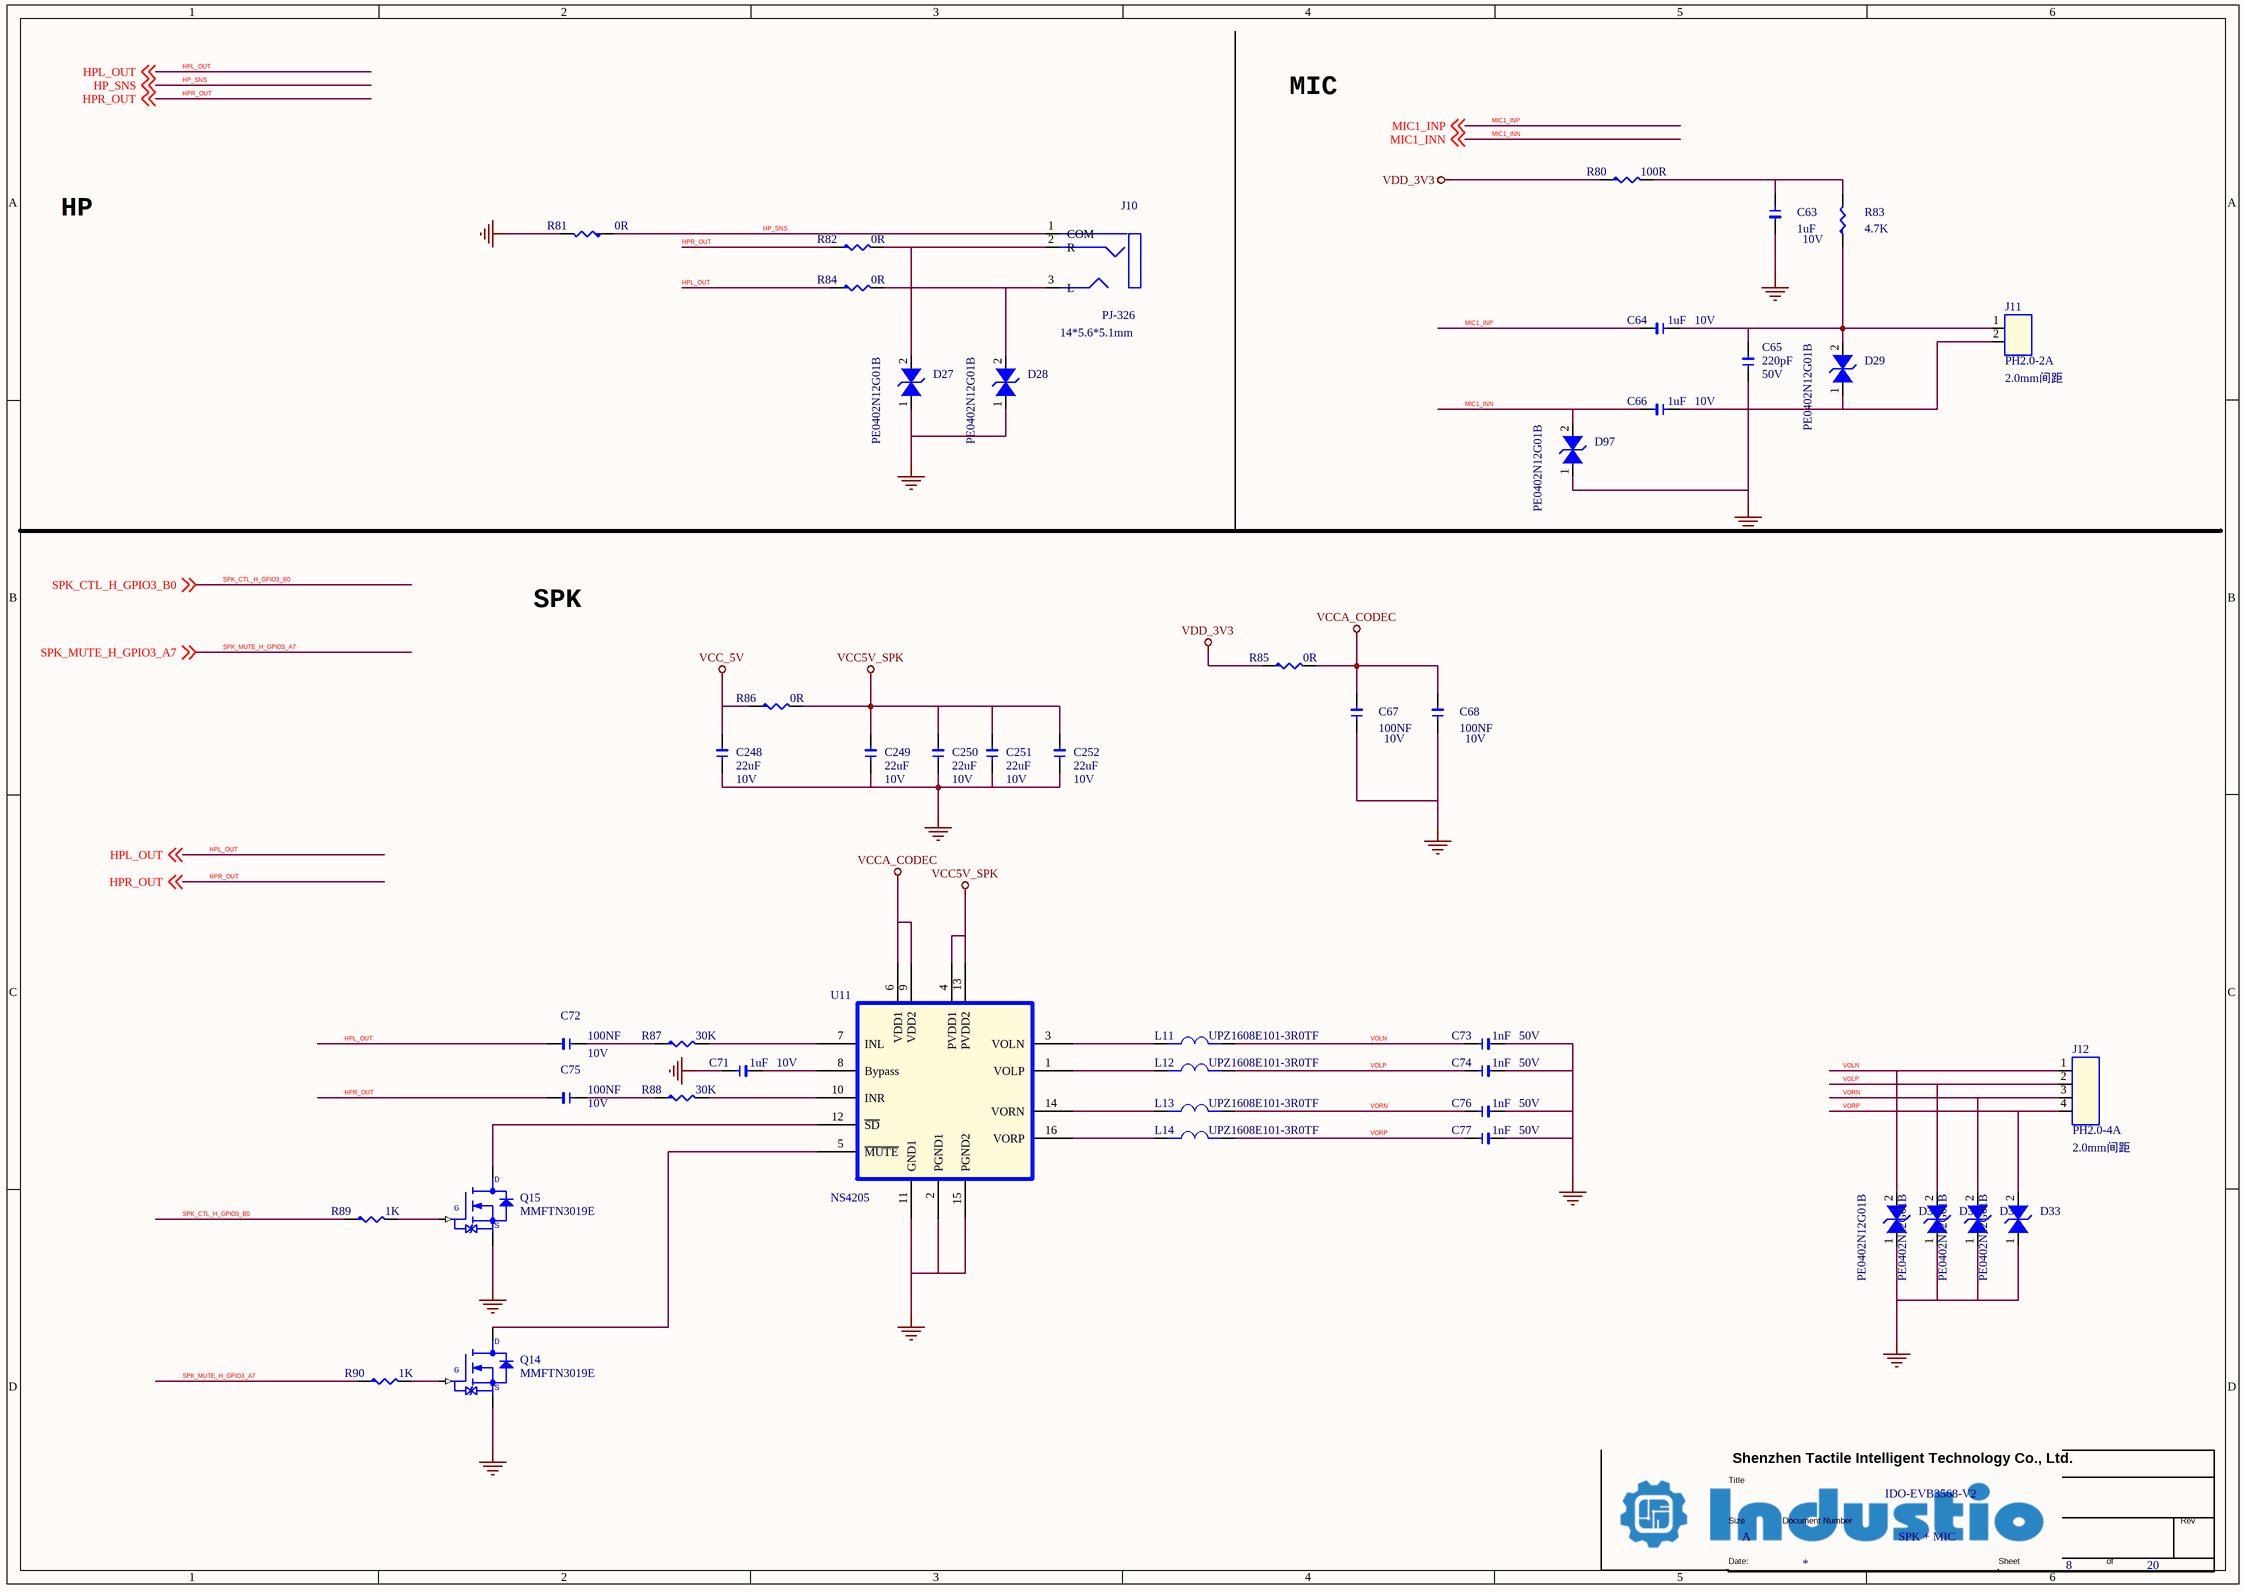
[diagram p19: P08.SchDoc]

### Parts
(Parts that share a designator on the sheet are numbered #1, #2 ... from top to bottom, then left to right.)
*#7  Doc: SPK + MIC  Title: IDO-EVB3568-V2  Page Size: A  Page Number: 8  Page Count: 20  (hidden comment: TitleBlock1)  (graphical)
C63  1uF  DSC2: 10V  [1206]
C64  1uF  DSC2: 10V  [1206]
C65  220pF  DSC2: 50V  [1206]
C66  1uF  DSC2: 10V  [1206]
C67  100NF  DSC2: 10V  [1206]
C68  100NF  DSC2: 10V  [1206]
C71  1uF  DSC2: 10V  [1206]
C72  100NF  DSC2: 10V  [1206]
C73  1nF  DSC2: 50V  [1206]
C74  1nF  DSC2: 50V  [1206]
C75  100NF  DSC2: 10V  [1206]
C76  1nF  DSC2: 50V  [1206]
C77  1nF  DSC2: 50V  [1206]
C248  22uF  DSC2: 10V  [1206]
C249  22uF  DSC2: 10V  [1206]
C250  22uF  DSC2: 10V  [1206]
C251  22uF  DSC2: 10V  [1206]
C252  22uF  DSC2: 10V  [1206]
D27  PE0402N12G01B  [V0402]
D28  PE0402N12G01B  [V0402]
D29  PE0402N12G01B  [V0402]
D30  PE0402N12G01B  [V0402]
D31  PE0402N12G01B  [V0402]
D32  PE0402N12G01B  [V0402]
D33  PE0402N12G01B  [V0402]
D97  PE0402N12G01B  [V0402]
J10  PJ-326  DSC2: 14*5.6*5.1mm  [PJ-326A-3P]
J11  PH2.0-2A  DSC2: 2.0mm间距  [PH200-2A]
J12  PH2.0-4A  DSC2: 2.0mm间距  [PH200-4A]
L11  UPZ1608E101-3R0TF  [L0603]
L12  UPZ1608E101-3R0TF  [L0603]
L13  UPZ1608E101-3R0TF  [L0603]
L14  UPZ1608E101-3R0TF  [L0603]
Q14  MMFTN3019E  [SOT523]
Q15  MMFTN3019E  [SOT523]
R80  100R  [R0402]
R81  0R  [R0402]
R82  0R  [R0402]
R83  4.7K  [R0402]
R84  0R  [R0402]
R85  0R  [R0603]
R86  0R  [R0805]
R87  30K  [R0402]
R88  30K  [R0402]
R89  1K  [R0402]
R90  1K  [R0402]
U11  NS4205  [SOP16-P127-390X990]

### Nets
GND: C63.2 C65.1 C66.1 C67.1 C68.1 C71.1 C73.2 C74.2 C76.2 C77.2 C248.1 C249.1 C250.1 C251.1 C252.1 D27.1(I/O2) D28.1(I/O2) D29.1(I/O2) D30.1(I/O2) D31.1(I/O2) D32.1(I/O2) D33.1(I/O2) D97.1(I/O2) J11.2 Q14.2(SOURCE) Q15.2(SOURCE) R81.2 U11.2(PGND1) U11.11(GND1) U11.15(PGND2)  [project net EDP_TX_AUXP_]
VCC5V_SPK: C249.2 C250.2 C251.2 C252.2 R86.2 U11.4(PVDD1) U11.13(PVDD2)
VCC_5V: C248.2 R86.1
VCCA_CODEC: C67.2 C68.2 R85.2 U11.6(VDD1) U11.9(VDD2)
VDD_3V3: R80.1 R85.1
HP_SNS: J10.1(COM) R81.1 ; off-sheet HP_SNS
HPL_OUT: C72.2 R84.1 ; off-sheet HPL_OUT
HPR_OUT: C75.2 R82.1 ; off-sheet HPR_OUT
MIC1_INN: C66.2 D97.2(I/O1) ; off-sheet MIC1_INN
MIC1_INP: C64.2 ; off-sheet MIC1_INP
SPK_CTL_H_GPIO3_B0: R89.1 ; off-sheet SPK_CTL_H_GPIO3_B0
SPK_MUTE_H_GPIO3_A7: R90.1 ; off-sheet SPK_MUTE_H_GPIO3_A7
VOLN: C73.1 D30.2(I/O1) J12.1 L11.2
VOLP: C74.1 D31.2(I/O1) J12.2 L12.2
VORN: C76.1 D32.2(I/O1) J12.3 L13.2
VORP: C77.1 D33.2(I/O1) J12.4 L14.2
NetC63_1: C63.1 R80.2 R83.2
NetC64_1: C64.1 C65.2 D29.2(I/O1) J11.1 R83.1
NetC71_2: C71.2 U11.8(Bypass)
NetC72_1: C72.1 R87.1
NetC75_1: C75.1 R88.1
NetD27_2: D27.2(I/O1) J10.2(R) R82.2
NetD28_2: D28.2(I/O1) J10.3(L) R84.2
NetL11_1: L11.1 U11.3(VOLN)
NetL12_1: L12.1 U11.1(VOLP)
NetL13_1: L13.1 U11.14(VORN)
NetL14_1: L14.1 U11.16(VORP)
NetQ14_1: Q14.1(GATE) R90.2
NetQ14_3: Q14.3(DRAIN) U11.5(~{MUTE})
NetQ15_1: Q15.1(GATE) R89.2
NetQ15_3: Q15.3(DRAIN) U11.12(~{SD})
NetR87_2: R87.2 U11.7(INL)
NetR88_2: R88.2 U11.10(INR)

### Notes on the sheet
- MIC
- HP
- SPK

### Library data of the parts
C63 = C-0402_Dup2: as C48 on sheet P07
C64 C66 = C-0402_Dup2: Part Number: C020102120064; Part Name: 贴片电容; Manufacture: 三星¦国巨¦村田; PCB Footprint: C0402; ERP Number: 1010200054; DSC1: ±10%; DSC3: X5R; ID: 64
C65 = C-0402_Dup1: Manufacture: 三星¦国巨¦村田; Part Name: 贴片电容; Part Number: C020102120045; ID: 45; DSC3: C0G; DSC1: ±5%; ERP Number: 1010200149; PCB Footprint: C0402
C67 C68 = C-0402_Dup1: Manufacture: 三星¦国巨¦村田; Part Name: 贴片电容; Part Number: C020102120060; ID: 60; DSC3: X7R; DSC1: ±10%; PCB Footprint: C0402
C71 = C-0402_Dup1: Manufacture: 三星¦国巨¦村田; Part Name: 贴片电容; Part Number: C020102120064; ID: 64; DSC3: X5R; DSC1: ±10%; ERP Number: 1010200054; PCB Footprint: C0402
C72 C75 = C-0402_Dup1: Part Number: C020102120060; Part Name: 贴片电容; Manufacture: 三星¦国巨¦村田; DSC1: ±10%; DSC3: X7R; ID: 60; PCB Footprint: C0402
C73 C74 C76 C77 = C-0402_Dup1: Part Number: C020102120054; Part Name: 贴片电容; Manufacture: 三星¦国巨¦村田; ERP Number: 1010200084; DSC1: ±10%; DSC3: X7R; ID: 54; PCB Footprint: C0402
C248 C250 C252 = C-0805: Manufacture: 三星¦国巨¦村田; Part Name: 贴片电容; Part Number: C020102120075; ID: 75; DSC3: X5R; DSC1: ±20%; PCB Footprint: C0603
C249 C251 = C-0805: Part Number: C020102120075; Part Name: 贴片电容; Manufacture: 三星¦国巨¦村田; DSC1: ±20%; DSC3: X5R; ID: 75; PCB Footprint: C0603
D27 D28 D30-D33 = DI-ESD: as D10 on sheet P07
D29 D97 = DI-ESD: as D7-D9 on sheet P07
J10 = J-PJ-326A-3P: Part Name: 音频耳机座; Part Number: J050502940003; P/N: 182K00300S; ID: 11; DSC4: PJ-326(星坤); DSC1: 3.5mm贴片式耳机座 凸头 3P 双定位柱
J11 = J-H-2P: Part Number: J020302820001; Part Name: PH; DSC1: 2p; DSC3: 通孔180度直针; DSC4: 米黄色胶壳 耐高温; DSC5: JLX-PH20-2A（九龙熹）; DSC6: X2016WV-02-46SN(星坤); ID: 11
J12 = J-H-4P: as J7 on sheet P07
L11-L14 = FB-0603: SMD Multilayer Ferrite Chip Bead,3A,30Ohm,0.03R; Part Number: C060502370005; Manufacture P/N: PZ1608D300-3R0TF; Manufacture2 P/N: PBY160808T-400Y-N; Manufacturer: SUNLORD; Manufacture: 顺络; Part Name: 贴片磁珠; PN Type: SMD FERRITE BEAD; ID: 5; DSC4: 电源线; DSC3: DCR=30mΩ; DSC1: 100Ω@100MHz; ERP Number: 1010200207
Q14 Q15 = N-MOS-Q_Dup1: as Q1 on sheet P07
R80 = R-0402_Dup4: Part Name: 贴片电阻; Part Number: C011002080279; ERP Number: 1010200160; DSC1: ±5%; DSC2: 1/16W; ID: 279
R81 R82 R84 = R-0402_Dup4: Part Name: 贴片电阻; Part Number: C011002080217; ERP Number: 1010200100; DSC1: ±5%; DSC2: 1/16W; ID: 217
R83 = R-0402_Dup4: Part Name: 贴片电阻; Part Number: C011002080320; ERP Number: 1010200177; DSC1: ±5%; DSC2: 1/16W; ID: 320
R85 = R-0603_Dup1: Part Number: C011002081182; Part Name: 贴片电阻; ID: 1,182; DSC2: 1/10W; DSC1: ±1%; ERP Number: 1010200158
R86 = R-0805_Dup1: Part Number: C011002081448; Part Name: 贴片电阻; ID: 1,448; DSC2: 1/8W; DSC1: ±1%; ERP Number: 1010200199
R87 R88 = R-0402_Dup4: Part Number: C011002080340; Part Name: 贴片电阻; ID: 340; DSC2: 1/16W; DSC1: ±5%
R89 = R-0402_Dup4: Part Number: C011002080303; Part Name: 贴片电阻; ID: 303; DSC2: 1/16W; DSC1: ±5%; ERP Number: 1010200104
R90 = R-0402_Dup4: Part Name: 贴片电阻; Part Number: C011002080303; ERP Number: 1010200104; DSC1: ±5%; DSC2: 1/16W; ID: 303
U11 = U-NS4205: Manufacture: Nsiway(纳芯威); Part Number: C150102670002; Part Name: 功放; ID: 2; DSC3: -40~85℃; DSC1: 2*3W @4Ω,3~5.2V，Class D; ERP Number: 1010100190

## Sheet P09.SchDoc
size 297 x 209 mm
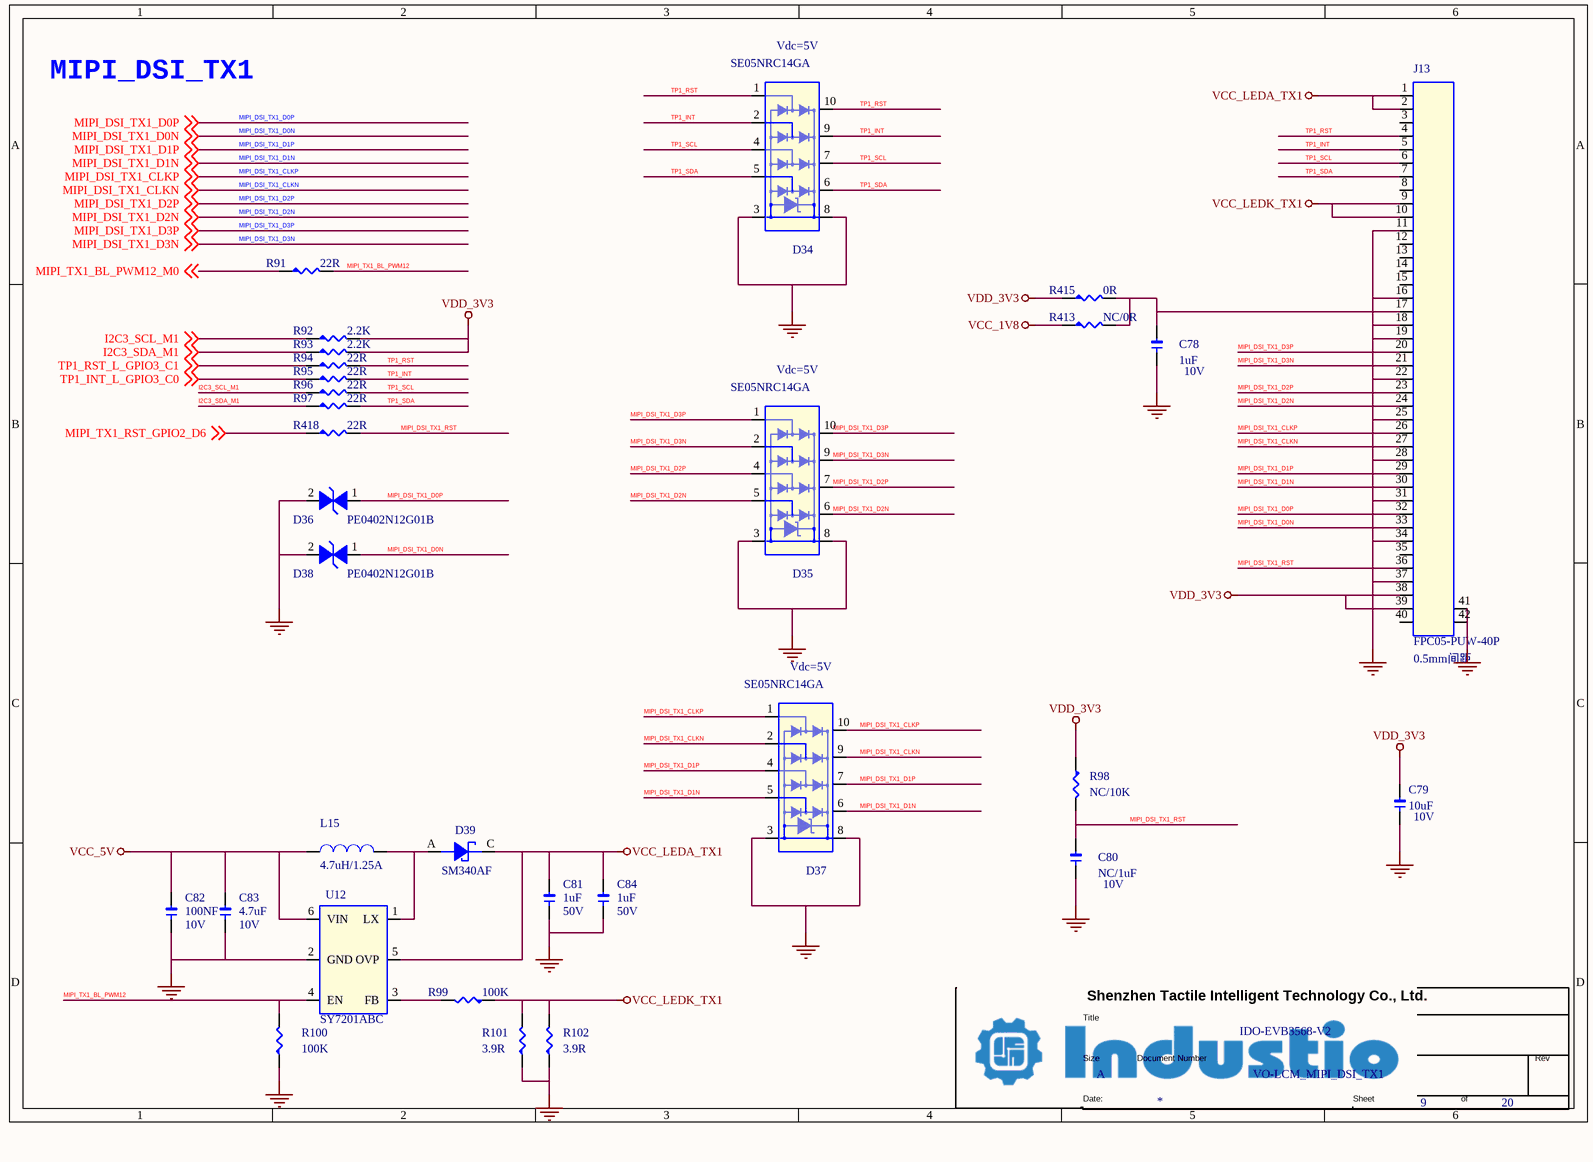
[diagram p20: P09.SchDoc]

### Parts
(Parts that share a designator on the sheet are numbered #1, #2 ... from top to bottom, then left to right.)
*#8  Doc: VO-LCM_MIPI_DSI_TX1  Title: IDO-EVB3568-V2  Page Size: A  Page Number: 9  Page Count: 20  (hidden comment: TitleBlock1)  (graphical)
C78  1uF  DSC2: 10V  [1206]
C79  10uF  DSC2: 10V  [1206]
C80  NC/1uF  DSC2: 10V  [1206]
C81  1uF  DSC2: 50V  [1206]
C82  100NF  DSC2: 10V  [1206]
C83  4.7uF  DSC2: 10V  [1206]
C84  1uF  DSC2: 50V  [1206]
D34  SE05NRC14GA  DSC2: Vdc=5V  [DFN2510-10L]
D35  SE05NRC14GA  DSC2: Vdc=5V  [DFN2510-10L]
D36  PE0402N12G01B  [V0402]
D37  SE05NRC14GA  DSC2: Vdc=5V  [DFN2510-10L]
D38  PE0402N12G01B  [V0402]
D39  SM340AF  [SMAF]
J13  FPC05-PUW-40P  DSC2: 0.5mm间距  [FPC05-40P]
L15  4.7uH/1.25A  [IND_252012]
R91  22R  [R0402]
R92  2.2K  [R0402]
R93  2.2K  [R0402]
R94  22R  [R0402]
R95  22R  [R0402]
R96  22R  [R0402]
R97  22R  [R0402]
R98  NC/10K  [R0402]
R99  100K  [R0402]
R100  100K  [R0402]
R101  3.9R  [R0603]
R102  3.9R  [R0603]
R413  NC/0R  [R0402]
R415  0R  [R0402]
R418  22R  [R0402]
U12  SY7201ABC  [SOT23-6]

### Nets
GND: C78.1 C79.1 C80.1 C81.1 C82.1 C83.1 C84.1 D34.3 D34.8 D35.3 D35.8 D36.2(I/O1) D37.3 D37.8 D38.2(I/O1) J13.11 J13.16 J13.18 J13.19 J13.22 J13.25 J13.28 J13.31 J13.34 J13.37 J13.41 J13.42 R100.1 R101.1 R102.1 U12.2(GND)  [project net EDP_TX_AUXP_]
VCC_1V8: R413.1
VCC_5V: C82.2 C83.2 L15.1 U12.6(VIN)
VCC_LEDA_TX1: C81.2 C84.2 D39.C J13.1 J13.2 U12.5(OVP)
VCC_LEDK_TX1: J13.9 J13.10 R99.1 R101.2 R102.2
VDD_3V3: C79.2 J13.38 J13.39 R92.2 R93.2 R98.1 R415.1
I2C3_SCL_M1: R92.1 R96.1 ; off-sheet I2C3_SCL_M1
I2C3_SDA_M1: R93.1 R97.1 ; off-sheet I2C3_SDA_M1
MIPI_DSI_TX1_CLKN: D37.2 D37.9 J13.27 ; off-sheet MIPI_DSI_TX1_CLKN
MIPI_DSI_TX1_CLKP: D37.1 D37.10 J13.26 ; off-sheet MIPI_DSI_TX1_CLKP
MIPI_DSI_TX1_D0N: D38.1(I/O2) J13.33 ; off-sheet MIPI_DSI_TX1_D0N
MIPI_DSI_TX1_D0P: D36.1(I/O2) J13.32 ; off-sheet MIPI_DSI_TX1_D0P
MIPI_DSI_TX1_D1N: D37.5 D37.6 J13.30 ; off-sheet MIPI_DSI_TX1_D1N
MIPI_DSI_TX1_D1P: D37.4 D37.7 J13.29 ; off-sheet MIPI_DSI_TX1_D1P
MIPI_DSI_TX1_D2N: D35.5 D35.6 J13.24 ; off-sheet MIPI_DSI_TX1_D2N
MIPI_DSI_TX1_D2P: D35.4 D35.7 J13.23 ; off-sheet MIPI_DSI_TX1_D2P
MIPI_DSI_TX1_D3N: D35.2 D35.9 J13.21 ; off-sheet MIPI_DSI_TX1_D3N
MIPI_DSI_TX1_D3P: D35.1 D35.10 J13.20 ; off-sheet MIPI_DSI_TX1_D3P
MIPI_DSI_TX1_RST: C80.2 J13.36 R98.2 R418.2
MIPI_TX1_BL_PWM12: R91.2 R100.2 U12.4(EN)
MIPI_TX1_BL_PWM12_M0: R91.1 ; off-sheet MIPI_TX1_BL_PWM12_M0
MIPI_TX1_RST_GPIO2_D6: R418.1 ; off-sheet MIPI_TX1_RST_GPIO2_D6
TP1_INT: D34.2 D34.9 J13.5 R95.2
TP1_INT_L_GPIO3_C0: R95.1 ; off-sheet TP1_INT_L_GPIO3_C0
TP1_RST: D34.1 D34.10 J13.4 R94.2
TP1_RST_L_GPIO3_C1: R94.1 ; off-sheet TP1_RST_L_GPIO3_C1
TP1_SCL: D34.4 D34.7 J13.6 R96.2
TP1_SDA: D34.5 D34.6 J13.7 R97.2
NetC78_2: C78.2 J13.17 R413.2 R415.2
NetD39_A: D39.A L15.2 U12.1(LX)
NetR99_2: R99.2 U12.3(FB)

Not connected (* = marked no-connect by the designer): J13 3 8 12 13 14 15 35 40

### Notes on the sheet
- MIPI_DSI_TX1

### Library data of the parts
C78 = C-0402_Dup1: Part Number: C020102120064; Part Name: 贴片电容; Manufacture: 三星¦国巨¦村田; ERP Number: 1010200054; DSC1: ±10%; DSC3: X5R; ID: 64; PCB Footprint: C0402
C79 = C-0603_Dup2: Part Number: C020102120071; Part Name: 贴片电容; Manufacture: 三星¦国巨¦村田; ERP Number: 1010200076; DSC1: ±20%; DSC3: X5R; ID: 71; PCB Footprint: C0603
C80 = C-0402_Dup1: Part Number: C020102120064; Part Name: 贴片电容; Manufacture: 三星¦国巨¦村田; PCB Footprint: C0402; ERP Number: 1010200054; DSC1: ±10%; DSC3: X5R; ID: 64
C81 = C-0603_Dup2: Manufacture: 三星¦国巨¦村田; Part Name: 贴片电容; Part Number: C020102120069; ID: 69; DSC3: X5R; DSC1: ±10%; ERP Number: 1010200142; PCB Footprint: C0603
C82 = C-0402_Dup2: Part Number: C020102120060; Part Name: 贴片电容; Manufacture: 三星¦国巨¦村田; DSC1: ±10%; DSC3: X7R; ID: 60; PCB Footprint: C0402
C83 = C-0402_Dup2: Manufacture: 三星¦国巨¦村田; Part Name: 贴片电容; Part Number: C020102120067; ID: 67; DSC3: X5R; DSC1: ±20%; PCB Footprint: C0402
C84 = C-0603_Dup2: Part Number: C020102120069; Part Name: 贴片电容; Manufacture: 三星¦国巨¦村田; ERP Number: 1010200142; DSC1: ±10%; DSC3: X5R; ID: 69; PCB Footprint: C0603
D34 D35 D37 = DI-ESD-SE05NRC14GA: as D17 on sheet P07
D36 = DI-ESD: as D7-D9 on sheet P07
D38 = DI-ESD: as D10 on sheet P07
D39 = DI-XI-S_Dup1: Part Number: C040202220007; Part Name: 肖特基二级管; Manufacture: 乐山无线电; CLASS: IC; DSC1: VR=40V; DSC2: IF=3A; DSC3: VF=500mV/3A; ID: 7; Solder: 推荐
J13 = J-FPC-40P: Part Number: J030102870037; Part Name: FPC座; DSC1: 40P; DSC3: 上接 抽拉式 卧贴; DSC4: H=2mm; DSC5: 镀锡; DSC6: X05B20U40T(星坤); ID: 10
L15 = L-IND: Manufacture: 宗成¦长江微电¦顺络; Part Name: 功率电感; ID: 54; DSC8: ZCRH252012-4.7uH-M(宗成); DSC7: FHD252012S-4R7MT(长江微电); DSC6: WPN252012H4R7MT(顺络); DSC5: 2.5*2.0*1.2mm; DSC4: 260mΩ; DSC3: Irms=1.25A; DSC2: Isat=1.6A; DSC1: ±20%
R91 R94-R97 = R-0402_Dup4: Part Name: 贴片电阻; Part Number: C011002080262; ERP Number: 1010200173; DSC1: ±5%; DSC2: 1/16W; ID: 262
R92 R93 = R-0402_Dup4: Part Number: C011002080311; Part Name: 贴片电阻; ID: 311; DSC2: 1/16W; DSC1: ±5%; ERP Number: 1010200170
R98 = R-0402_Dup4: as R58 on sheet P07
R99 = R-0402_Dup4: Part Number: C011002080353; Part Name: 贴片电阻; ID: 353; DSC2: 1/16W; DSC1: ±5%; ERP Number: 1010200103
R100 = R-0402_Dup4: as R30 on sheet P07
R101 = R-0603_Dup1: Part Name: 贴片电阻; Part Number: C011002081232; DSC1: ±1%; DSC2: 1/10W; ID: 1,232
R102 = R-0603_Dup1: Part Number: C011002081232; Part Name: 贴片电阻; ID: 1,232; DSC2: 1/10W; DSC1: ±1%
R413 R415 = R-0402_Dup4: as R81 on sheet P08
R418 = R-0402_Dup4: as R32 on sheet P07
U12 = U-SY7201A_2: Manufacture: 矽力杰; Part Number: C070202410024; Part Name: DCDC; ID: 24; Solder: 量产; DSC7: Boost LED驱动; DSC6: 1MHz; DSC5: 0.9; DSC4: Vfb=200mV; DSC3: Io=2A; DSC1: Vi=2.5-30V; ERP Number: 1010100053

## Sheet P10.SchDoc
size 297 x 209 mm
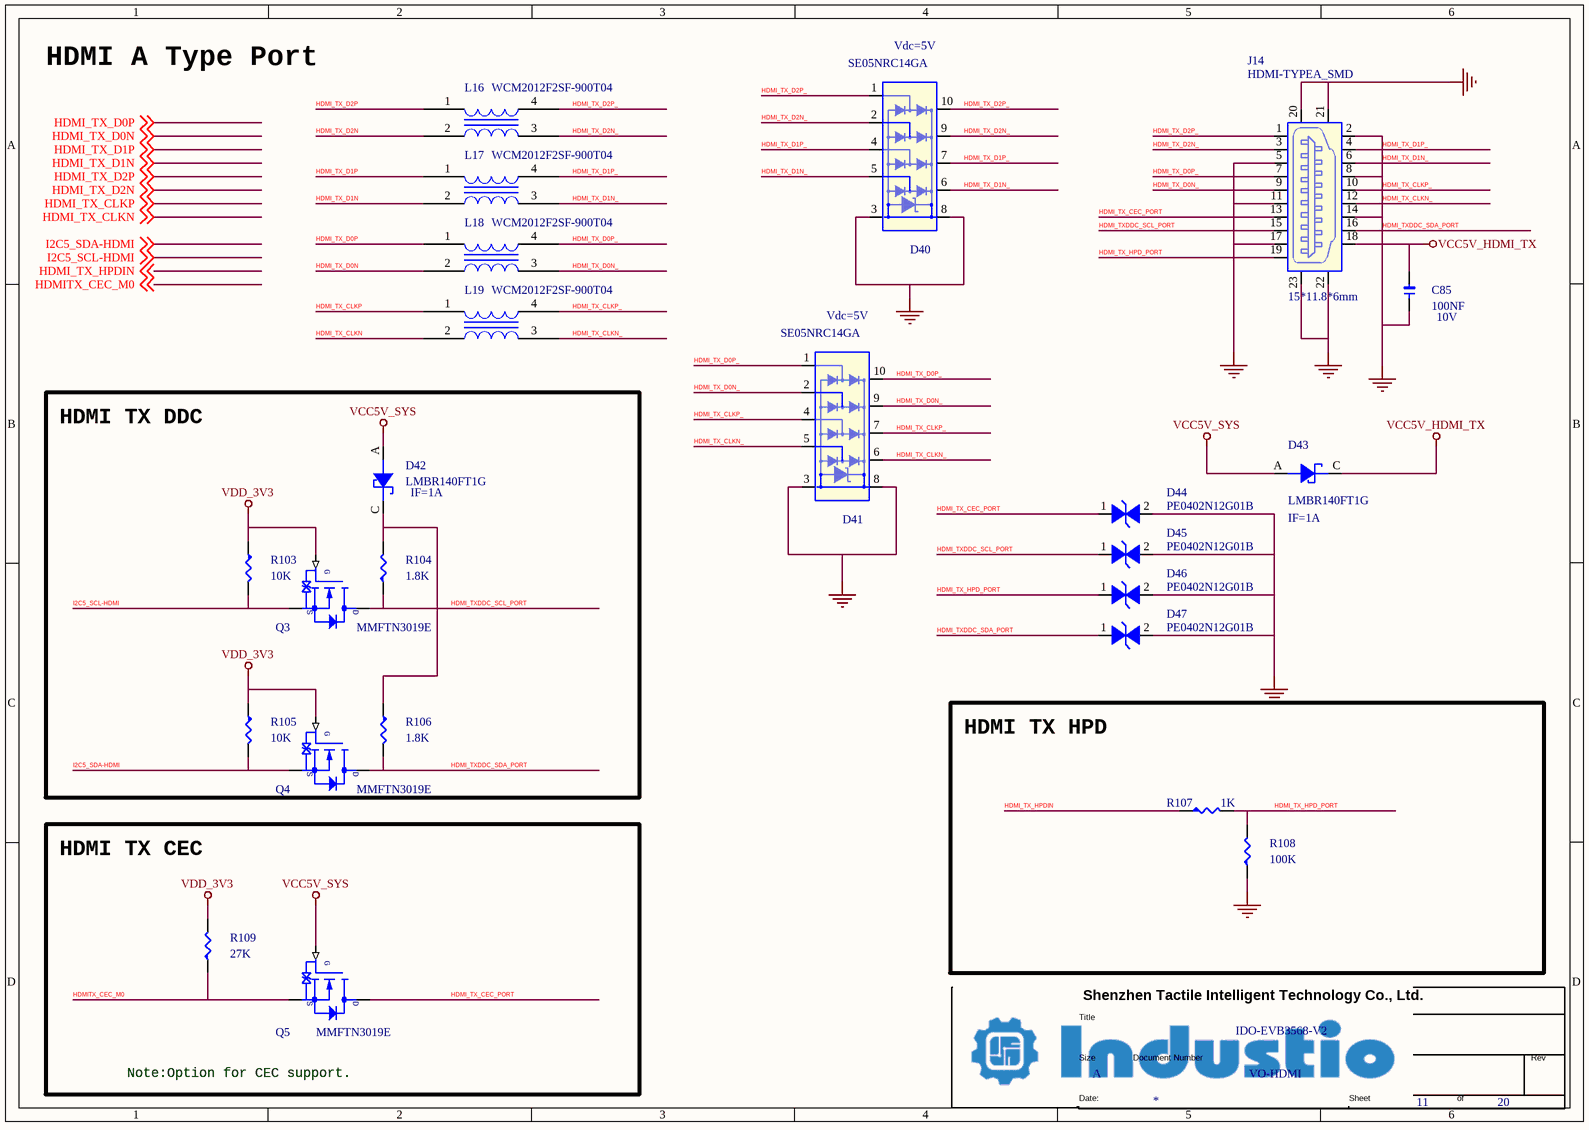
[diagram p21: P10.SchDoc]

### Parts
(Parts that share a designator on the sheet are numbered #1, #2 ... from top to bottom, then left to right.)
*#9  Doc: VO-HDMI  Title: IDO-EVB3568-V2  Page Size: A  Page Number: 11  Page Count: 20  (hidden comment: TitleBlock1)  (graphical)
C85  100NF  DSC2: 10V  [1206]
D40  SE05NRC14GA  DSC2: Vdc=5V  [DFN2510-10L]
D41  SE05NRC14GA  DSC2: Vdc=5V  [DFN2510-10L]
D42  LMBR140FT1G  DSC2: IF=1A  [SOD-123F]
D43  LMBR140FT1G  DSC2: IF=1A  [SOD-123F]
D44  PE0402N12G01B  [V0402]
D45  PE0402N12G01B  [V0402]
D46  PE0402N12G01B  [V0402]
D47  PE0402N12G01B  [V0402]
J14  HDMI-TYPEA_SMD  DSC2: 15*11.8*6mm  [HDMI-TYPEA_SMD]
L16  WCM2012F2SF-900T04  [CMLS-ACM2012]
L17  WCM2012F2SF-900T04  [CMLS-ACM2012]
L18  WCM2012F2SF-900T04  [CMLS-ACM2012]
L19  WCM2012F2SF-900T04  [CMLS-ACM2012]
Q3  MMFTN3019E  [SOT523]
Q4  MMFTN3019E  [SOT523]
Q5  MMFTN3019E  [SOT523]
R103  10K  [R0402]
R104  1.8K  [R0402]
R105  10K  [R0402]
R106  1.8K  [R0402]
R107  1K  [R0402]
R108  100K  [R0402]
R109  27K  [R0402]

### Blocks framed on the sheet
HDMI TX DDC: D42 Q3 Q4 R103-R106
HDMI TX HPD: R107 R108
HDMI TX CEC: Q5 R109

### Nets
GND: C85.1 D40.3 D40.4 D40.5 D40.6 D40.7 D40.8 D41.3 D41.4 D41.5 D41.6 D41.7 D41.8 D44.2(I/O1) D45.2(I/O1) D46.2(I/O1) D47.1(I/O2) D47.2(I/O1) J14.2 J14.4 J14.5 J14.6 J14.8 J14.10 J14.11 J14.12 J14.14 J14.16 J14.17 J14.20 J14.21 J14.22 J14.23 L17.3 L17.4 L19.3 L19.4 Q4.3(DRAIN) R106.2 R108.1  [also labelled HDMI_TX_CLKN_, HDMI_TX_CLKP_, HDMI_TX_D1N_, HDMI_TX_D1P_, HDMI_TXDDC_SDA_PORT]  [project net EDP_TX_AUXP_]
VCC5V_HDMI_TX: C85.2 D43.C J14.18
VCC5V_SYS: D42.A D43.A Q5.1(GATE)
VDD_3V3: Q3.1(GATE) Q4.1(GATE) R103.1 R105.1 R109.2
HDMI_TX_CEC_PORT: D44.1(I/O2) J14.13 Q5.3(DRAIN)
HDMI_TX_CLKN: L19.2 ; off-sheet HDMI_TX_CLKN
HDMI_TX_CLKP: L19.1 ; off-sheet HDMI_TX_CLKP
HDMI_TX_D0N: L18.2 ; off-sheet HDMI_TX_D0N
HDMI_TX_D0N_: D41.2 D41.9 J14.9 L18.3
HDMI_TX_D0P: L18.1 ; off-sheet HDMI_TX_D0P
HDMI_TX_D0P_: D41.1 D41.10 J14.7 L18.4
HDMI_TX_D1N: L17.2 ; off-sheet HDMI_TX_D1N
HDMI_TX_D1P: L17.1 ; off-sheet HDMI_TX_D1P
HDMI_TX_D2N: L16.2 ; off-sheet HDMI_TX_D2N
HDMI_TX_D2N_: D40.2 D40.9 J14.3 L16.3
HDMI_TX_D2P: L16.1 ; off-sheet HDMI_TX_D2P
HDMI_TX_D2P_: D40.1 D40.10 J14.1($PIN0) L16.4
HDMI_TX_HPD_PORT: D46.1(I/O2) J14.19 R107.2 R108.2
HDMI_TX_HPDIN: R107.1 ; off-sheet HDMI_TX_HPDIN
HDMI_TXDDC_SCL_PORT: D45.1(I/O2) J14.15 Q3.3(DRAIN) R104.1
HDMITX_CEC_M0: Q5.2(SOURCE) R109.1 ; off-sheet HDMITX_CEC_M0
I2C5_SCL-HDMI: Q3.2(SOURCE) R103.2 ; off-sheet I2C5_SCL-HDMI
I2C5_SDA-HDMI: Q4.2(SOURCE) R105.2 ; off-sheet I2C5_SDA-HDMI
NetD42_C: D42.C R104.2 R106.1

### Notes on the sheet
- HDMI A Type Port
- Note:Option for CEC support.

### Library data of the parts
C85 = C-0402_Dup1: Part Number: C020102120060; Part Name: 贴片电容; Manufacture: 三星¦国巨¦村田; PCB Footprint: C0402; DSC1: ±10%; DSC3: X7R; ID: 60
D40 = DI-ESD-SE05NRC14GA: as D14 on sheet P07
D41 = DI-ESD-SE05NRC14GA: as D17 on sheet P07
D42 D43 = DI-XI-S: Manufacture: 乐山无线电; Part Name: 肖特基二级管; Part Number: C040205134719; CLASS: IC; ID: 17; DSC4: IR=3uA; DSC3: VF=540mV/1A; DSC1: VR=40V
D44 D45 = DI-ESD: as D10 on sheet P07
D46 D47 = DI-ESD: as D7-D9 on sheet P07
J14 = J-HDMI-19P: Part Number: J050302920001; Part Name: HDMI座; DSC1: HDMI 19P母座SMD铜壳四脚 黑胶LCP 耐高温; DSC3: 贴片; DSC4: JLX-HDMI-002（九龙熹）; DSC5: A71-05H9-111N1（星坤）; ID: 7
L16-L19 = L-CMLS-ACM2012: as L5 on sheet P07
Q3 Q5 = N-MOS-Q_Dup1: Part Number: C030202190004; Part Name: N-MOS; Manufacture: 先科; ERP Number: 1010800011; DSC1: Vds=30V; DSC2: Id=100mA; DSC3: Vgs(th)=1.5V; DSC4: Vgs=±20V; DSC5: pd=150mW; ID: 4
Q4 = N-MOS-Q_Dup1: as Q1 on sheet P07
R103 R105 = R-0402_Dup4: as R58 on sheet P07
R104 R106 = R-0402_Dup4: Part Number: C011002080309; Part Name: 贴片电阻; ID: 309; DSC2: 1/16W; DSC1: ±5%
R107 = R-0402_Dup4: as R89 on sheet P08
R108 = R-0402_Dup4: as R99 on sheet P09
R109 = R-0402_Dup4: Part Number: C011002080338; Part Name: 贴片电阻; ID: 338; DSC2: 1/16W; DSC1: ±5%; ERP Number: 1010200461

## Sheet P11.SchDoc
size 594 x 420 mm
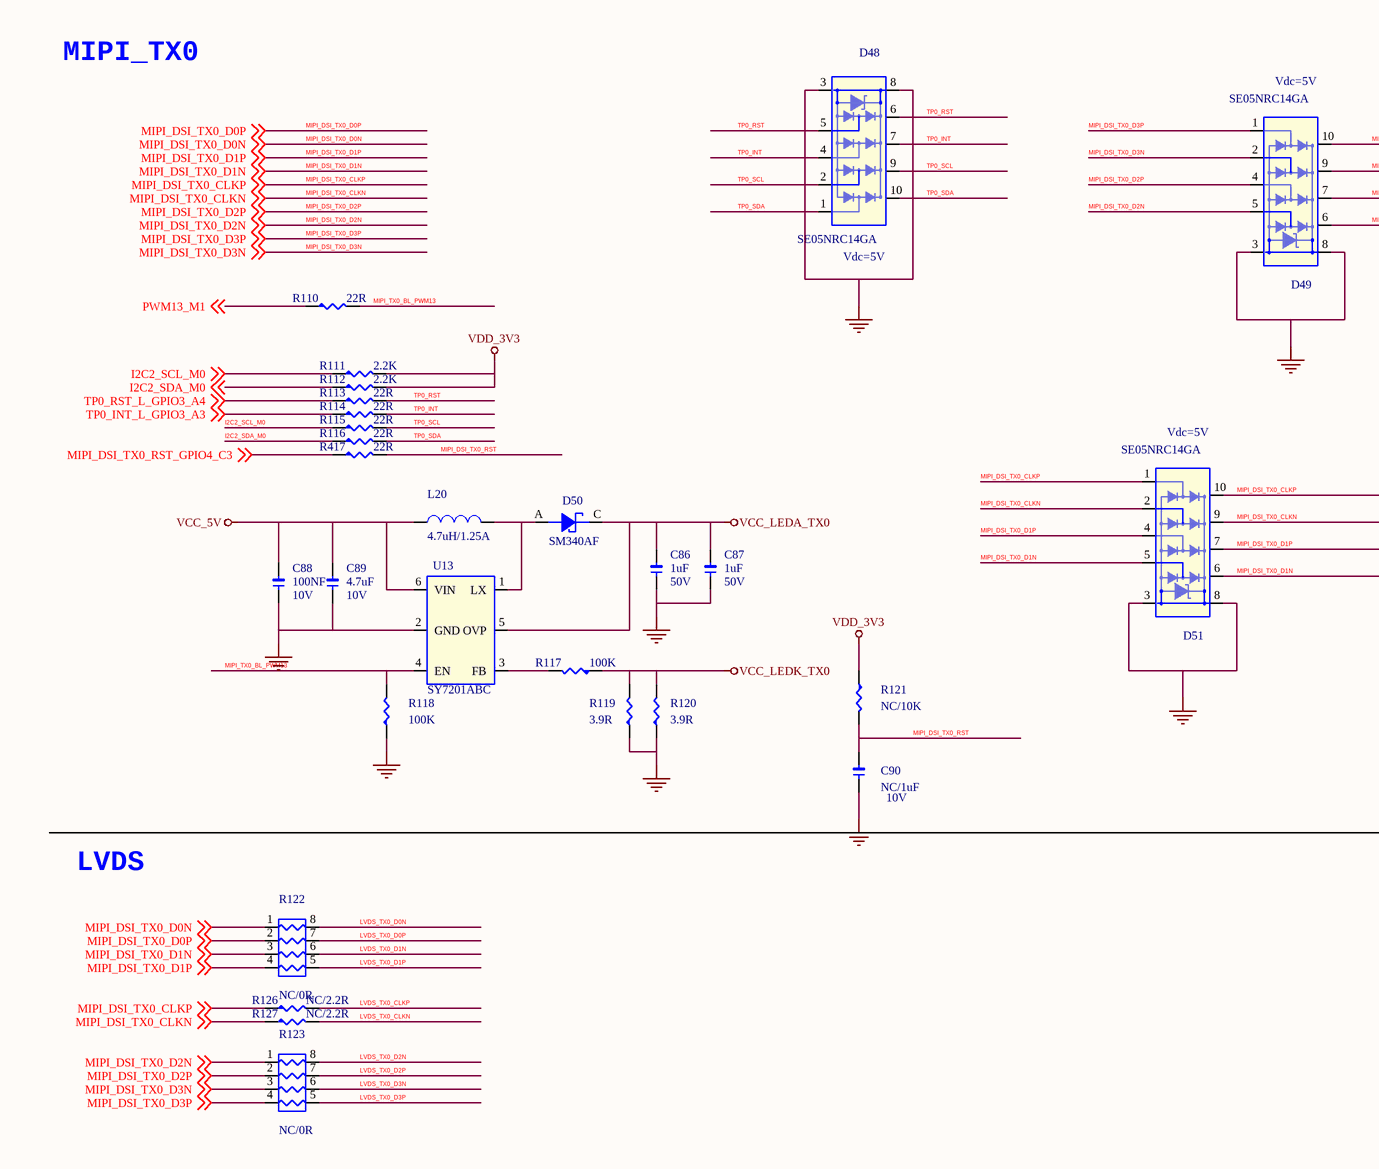
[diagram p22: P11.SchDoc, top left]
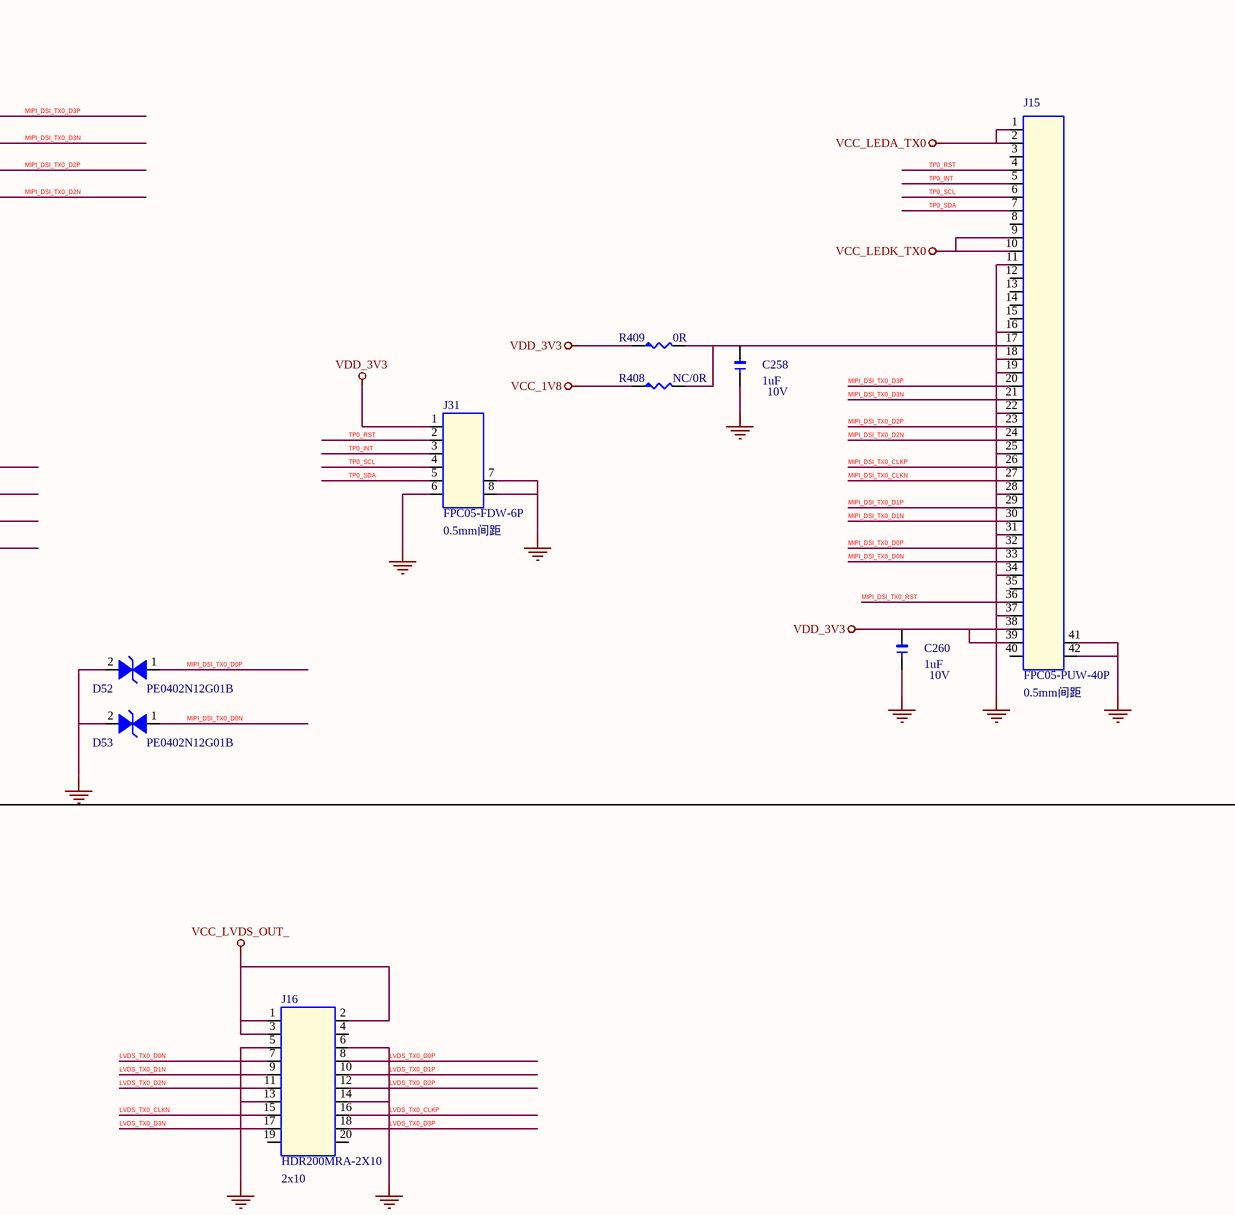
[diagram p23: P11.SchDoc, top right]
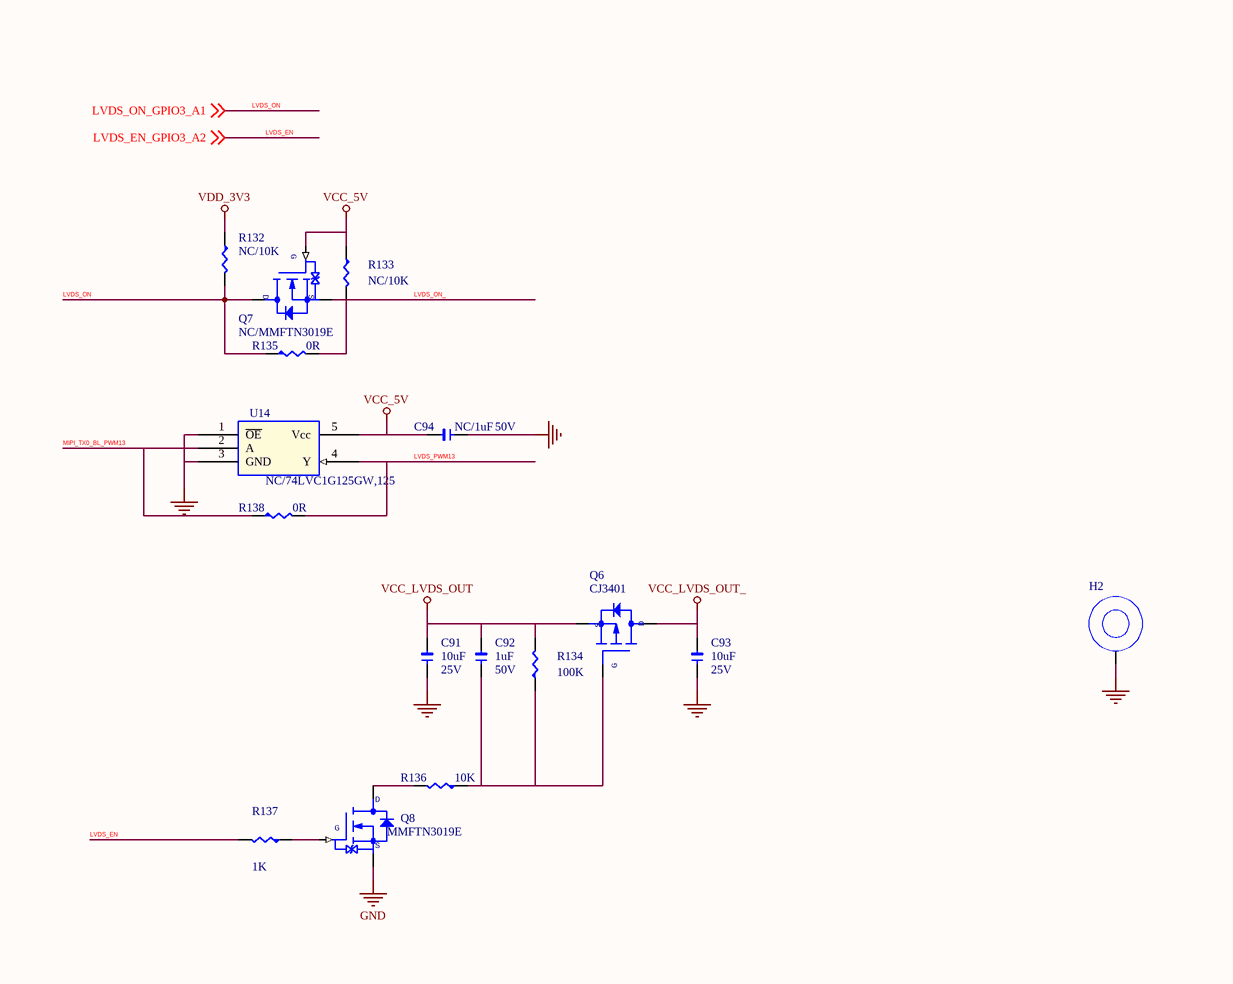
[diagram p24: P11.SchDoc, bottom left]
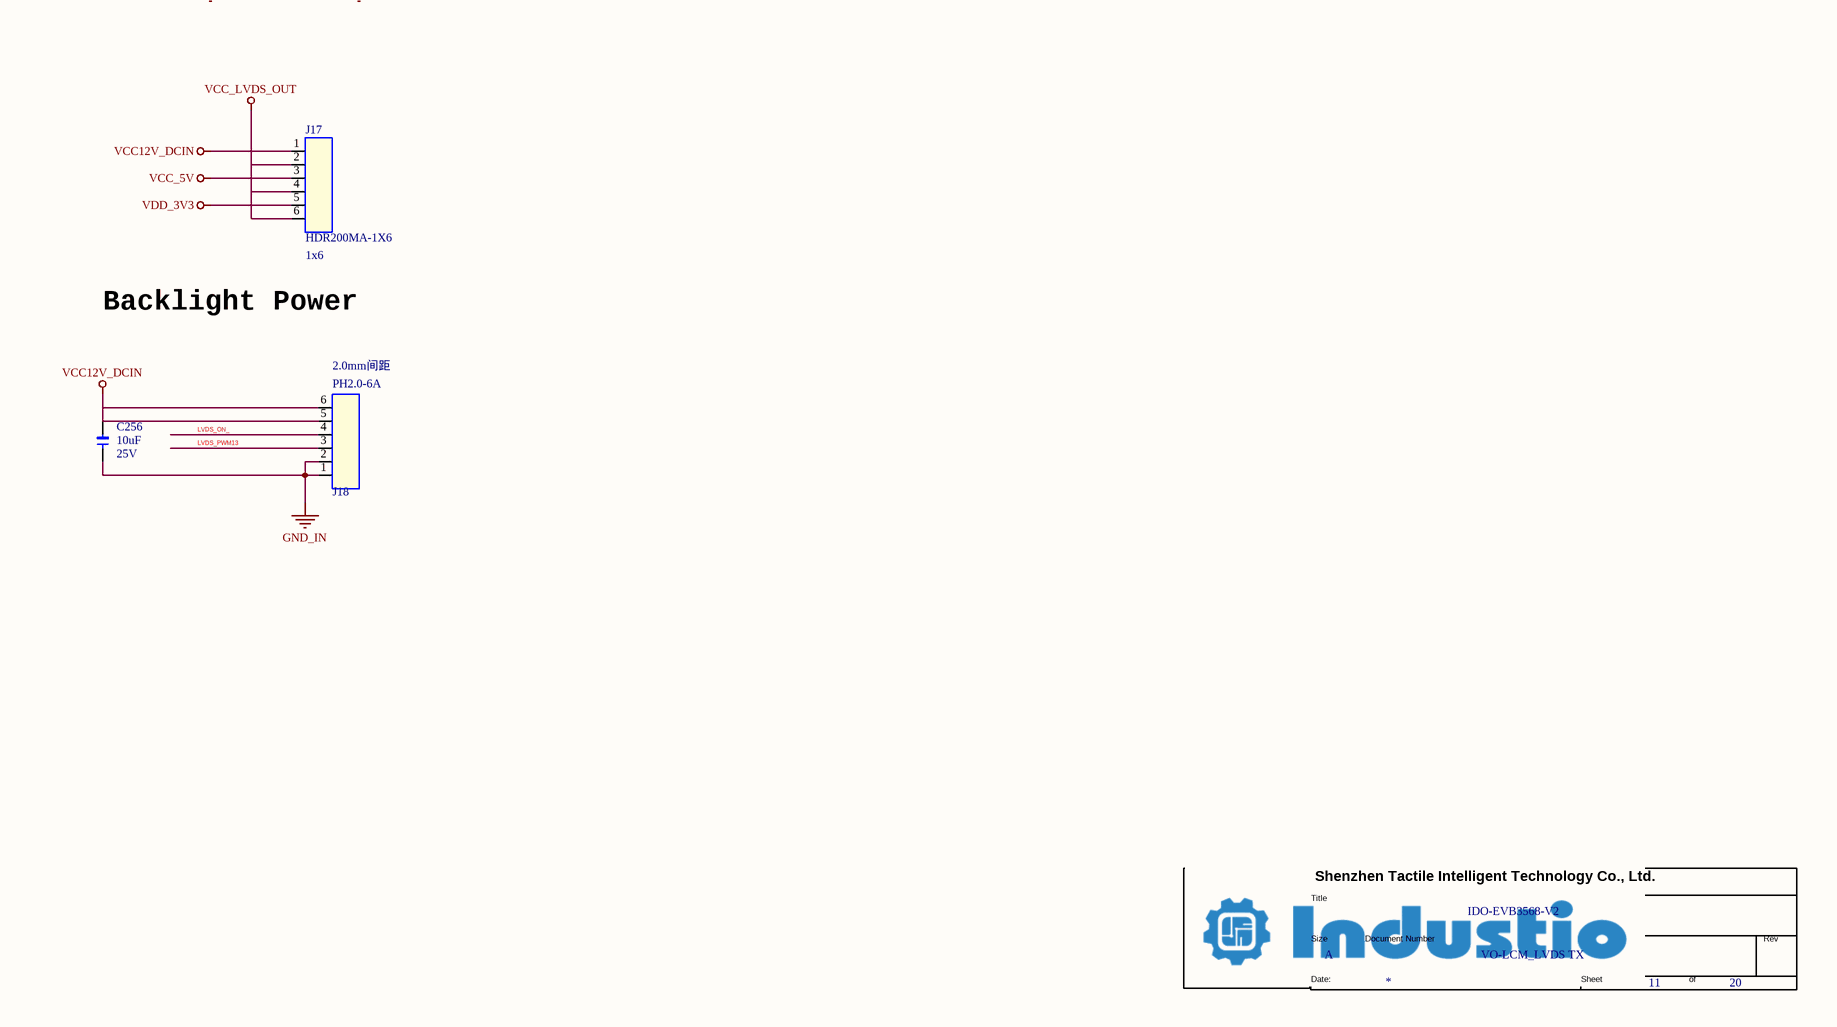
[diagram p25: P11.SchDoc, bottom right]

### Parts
(Parts that share a designator on the sheet are numbered #1, #2 ... from top to bottom, then left to right.)
*#10  Doc: VO-LCM_LVDS TX  Title: IDO-EVB3568-V2  Page Size: A  Page Number: 11  Page Count: 20  (hidden comment: TitleBlock1)  (graphical)
C86  1uF  DSC2: 50V  [1206]
C87  1uF  DSC2: 50V  [1206]
C88  100NF  DSC2: 10V  [1206]
C89  4.7uF  DSC2: 10V  [1206]
C90  NC/1uF  DSC2: 10V  [1206]
C91  10uF  DSC2: 25V  [1206]
C92  1uF  DSC2: 50V  [1206]
C93  10uF  DSC2: 25V  [1206]
C94  NC/1uF  DSC2: 50V  [1206]
C256  10uF  DSC2: 25V  [1206]
C258  1uF  DSC2: 10V  [1206]
C260  1uF  DSC2: 10V  [1206]
D48  SE05NRC14GA  DSC2: Vdc=5V  [DFN2510-10L]
D49  SE05NRC14GA  DSC2: Vdc=5V  [DFN2510-10L]
D50  SM340AF  [SMAF]
D51  SE05NRC14GA  DSC2: Vdc=5V  [DFN2510-10L]
D52  PE0402N12G01B  [V0402]
D53  PE0402N12G01B  [V0402]
H2  Hole  [MTG430_620_SMTSO_M3]  (value not drawn)
J15  FPC05-PUW-40P  DSC2: 0.5mm间距  [FPC05-40P]
J16  HDR200MRA-2X10  DSC2: 2x10  [HDR200MRA-2X10]
J17  HDR200MA-1X6  DSC2: 1x6  [HDR200MA-1X6]
J18  PH2.0-6A  DSC2: 2.0mm间距  [PH200-6A]
J31  FPC05-FDW-6P  DSC2: 0.5mm间距  [FPC05-6P]
L20  4.7uH/1.25A  [IND_252012]
Q6  CJ3401  [SOT23]
Q7  NC/MMFTN3019E  [SOT523]
Q8  MMFTN3019E  [SOT523]
R110  22R  [R0402]
R111  2.2K  [R0402]
R112  2.2K  [R0402]
R113  22R  [R0402]
R114  22R  [R0402]
R115  22R  [R0402]
R116  22R  [R0402]
R117  100K  [R0402]
R118  100K  [R0402]
R119  3.9R  [R0603]
R120  3.9R  [R0603]
R121  NC/10K  [R0402]
R122  NC/0R  [RN_0402X4]
R123  NC/0R  [RN_0402X4]
R126  NC/2.2R  [R0402]
R127  NC/2.2R  [R0402]
R132  NC/10K  [R0402]
R133  NC/10K  [R0402]
R134  100K  [R0402]
R135  0R  [R0402]
R136  10K  [R0402]
R137  1K  [R0402]
R138  0R  [R0402]
R408  NC/0R  [R0402]
R409  0R  [R0402]
R417  22R  [R0402]
U13  SY7201ABC  [SOT23-6]
U14  NC/74LVC1G125GW,125  [SOT353]

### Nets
GND: C86.1 C87.1 C88.1 C89.1 C90.1 C91.1 C93.1 C94.1 C258.1 C260.1 D48.3 D48.8 D49.3 D49.8 D51.3 D51.8 D52.2(I/O1) D53.2(I/O1) H2.1 J15.11 J15.16 J15.18 J15.19 J15.22 J15.25 J15.28 J15.31 J15.34 J15.37 J15.41 J15.42 J16.5 J16.6 J16.8 J16.10 J16.12 J16.13 J16.14 J16.16 J16.18 J31.6 J31.7 J31.8 Q8.2(SOURCE) R118.1 R119.1 R120.1 R122.5 R122.7 R123.5 R123.7 R126.2 U13.2(GND) U14.1(~{OE}) U14.3(GND)  [also labelled LVDS_TX0_CLKP, LVDS_TX0_D0P, LVDS_TX0_D1P, LVDS_TX0_D2P, LVDS_TX0_D3P]  [project net EDP_TX_AUXP_]
GND_IN: C256.1 J18.1 J18.2
VCC12V_DCIN: C256.2 J17.1 J18.5 J18.6
VCC_1V8: R408.1
VCC_5V: C88.2 C89.2 C94.2 J17.3 L20.1 Q7.1(GATE) R133.1 U13.6(VIN) U14.5(Vcc)
VCC_LEDA_TX0: C86.2 C87.2 D50.C J15.1 J15.2 U13.5(OVP)
VCC_LEDK_TX0: J15.9 J15.10 R117.1 R119.2 R120.2
VCC_LVDS_OUT: C91.2 C92.2 J17.2 J17.4 J17.6 Q6.2(SOURCE) R134.2
VCC_LVDS_OUT_: C93.2 J16.1 J16.2 J16.3 Q6.3(DRAIN)
VDD_3V3: C260.2 J15.38 J15.39 J17.5 J31.1 R111.2 R112.2 R121.1 R132.1 R409.1
I2C2_SCL_M0: R111.1 R115.1 ; off-sheet I2C2_SCL_M0
I2C2_SDA_M0: R112.1 R116.1 ; off-sheet I2C2_SDA_M0
LVDS_EN: R137.2 ; off-sheet LVDS_EN_GPIO3_A2  [also labelled LVDS_EN_GPIO3_A2]
LVDS_ON: Q7.3(DRAIN) R132.2 R135.1 ; off-sheet LVDS_ON_GPIO3_A1  [also labelled LVDS_ON_GPIO3_A1]
LVDS_ON_: J18.4 Q7.2(SOURCE) R133.2 R135.2
LVDS_PWM13: J18.3 R138.2 U14.4(Y)
LVDS_TX0_CLKN: J16.15 R127.2
LVDS_TX0_D0N: J16.7 R122.8
LVDS_TX0_D1N: J16.9 R122.6
LVDS_TX0_D2N: J16.11 R123.8
LVDS_TX0_D3N: J16.17 R123.6
MIPI_DSI_TX0_CLKN: D51.2 D51.9 J15.27 R127.1 ; off-sheet MIPI_DSI_TX0_CLKN
MIPI_DSI_TX0_CLKP: D51.1 D51.10 J15.26 R126.1 ; off-sheet MIPI_DSI_TX0_CLKP
MIPI_DSI_TX0_D0N: D53.1(I/O2) J15.33 R122.1 ; off-sheet MIPI_DSI_TX0_D0N
MIPI_DSI_TX0_D0P: D52.1(I/O2) J15.32 R122.2 ; off-sheet MIPI_DSI_TX0_D0P
MIPI_DSI_TX0_D1N: D51.5 D51.6 J15.30 R122.3 ; off-sheet MIPI_DSI_TX0_D1N
MIPI_DSI_TX0_D1P: D51.4 D51.7 J15.29 R122.4 ; off-sheet MIPI_DSI_TX0_D1P
MIPI_DSI_TX0_D2N: D49.5 D49.6 J15.24 R123.1 ; off-sheet MIPI_DSI_TX0_D2N
MIPI_DSI_TX0_D2P: D49.4 D49.7 J15.23 R123.2 ; off-sheet MIPI_DSI_TX0_D2P
MIPI_DSI_TX0_D3N: D49.2 D49.9 J15.21 R123.3 ; off-sheet MIPI_DSI_TX0_D3N
MIPI_DSI_TX0_D3P: D49.1 D49.10 J15.20 R123.4 ; off-sheet MIPI_DSI_TX0_D3P
MIPI_DSI_TX0_RST: C90.2 J15.36 R121.2 R417.2
MIPI_DSI_TX0_RST_GPIO4_C3: R417.1 ; off-sheet MIPI_DSI_TX0_RST_GPIO4_C3
MIPI_TX0_BL_PWM13: R110.2 R118.2 R138.1 U13.4(EN) U14.2(A)
PWM13_M1: R110.1 ; off-sheet PWM13_M1
TP0_INT: D48.4 D48.7 J15.5 J31.3 R114.2
TP0_INT_L_GPIO3_A3: R114.1 ; off-sheet TP0_INT_L_GPIO3_A3
TP0_RST: D48.5 D48.6 J15.4 J31.2 R113.2
TP0_RST_L_GPIO3_A4: R113.1 ; off-sheet TP0_RST_L_GPIO3_A4
TP0_SCL: D48.2 D48.9 J15.6 J31.4 R115.2
TP0_SDA: D48.1 D48.10 J15.7 J31.5 R116.2
NetC92_1: C92.1 Q6.1(GATE) R134.1 R136.1
NetC258_2: C258.2 J15.17 R408.2 R409.2
NetD50_A: D50.A L20.2 U13.1(LX)
NetQ8_1: Q8.1(GATE) R137.1
NetQ8_3: Q8.3(DRAIN) R136.2
NetR117_2: R117.2 U13.3(FB)

Not connected (* = marked no-connect by the designer): J15 3 8 12 13 14 15 35 40; J16 4 19 20

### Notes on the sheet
- MIPI_TX0
- LVDS
- Backlight Power

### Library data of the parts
C86 = C-0603_Dup2: as C84 on sheet P09
C87 C92 C94 = C-0603_Dup2: as C81 on sheet P09
C88 = C-0402_Dup2: Manufacture: 三星¦国巨¦村田; Part Name: 贴片电容; Part Number: C020102120060; ID: 60; DSC3: X7R; DSC1: ±10%; PCB Footprint: C0402
C89 = C-0402_Dup2: Part Number: C020102120067; Part Name: 贴片电容; Manufacture: 三星¦国巨¦村田; DSC1: ±20%; DSC3: X5R; ID: 67; PCB Footprint: C0402
C90 = C-0402_Dup1: as C71 on sheet P08
C91 = C-0805_Dup1: Part Number: C020102120074; Part Name: 贴片电容; Manufacture: 三星¦国巨¦村田; ERP Number: 1010200144; DSC1: ±10%; DSC3: X5R; ID: 74; PCB Footprint: C0805
C93 C256 = C-0805_Dup1: Manufacture: 三星¦国巨¦村田; Part Name: 贴片电容; Part Number: C020102120074; ID: 74; DSC3: X5R; DSC1: ±10%; ERP Number: 1010200144; PCB Footprint: C0805
C258 C260 = C-0402_Dup1: Manufacture: 三星¦国巨¦村田; Part Name: 贴片电容; Part Number: C020102120064; PCB Footprint: C0402; ID: 64; DSC3: X5R; DSC1: ±10%; ERP Number: 1010200054
D48 D49 = DI-ESD-SE05NRC14GA: as D14 on sheet P07
D50 = DI-XI-S_Dup1: Manufacture: 乐山无线电; Part Name: 肖特基二级管; Part Number: C040202220007; CLASS: IC; Solder: 推荐; ID: 7; DSC3: VF=500mV/3A; DSC2: IF=3A; DSC1: VR=40V
D51 = DI-ESD-SE05NRC14GA: as D17 on sheet P07
D52 = DI-ESD: as D10 on sheet P07
D53 = DI-ESD: as D7-D9 on sheet P07
J15 = J-FPC-40P: Part Name: FPC座; Part Number: J030102870037; ID: 10; DSC6: X05B20U40T(星坤); DSC5: 镀锡; DSC4: H=2mm; DSC3: 上接 抽拉式 卧贴; DSC1: 40P
J16 = J-HDR-D-20: Part Number: J010102760085; Part Name: 双排针; DSC1: 双排单塑; DSC3: 2mm脚距; DSC4: 通孔弯针; DSC5: 2.8+2(H塑高)+4 mm; DSC6: 黑胶; DSC7: X4621WR-2x10I-C28D40（星坤）; ID: 29
J17 = J-HDR-6: Part Number: J010206123880; Part Name: 单排针; DSC1: 单排单塑; DSC3: 2mm脚距; DSC4: 通孔直针; DSC5: 针长8.8mm  2.8+2(H塑高)+4 mm; DSC6: 黑胶; DSC7: X4611WV-06I-C28D40（星坤）; ID: 66
J18 = J-H-6P: Part Name: PH; Part Number: J020302820005; ID: 15; DSC6: X2016WV-06-46SN(星坤); DSC5: JLX-PH20-6A（九龙熹）; DSC4: 米黄色胶壳 耐高温; DSC3: 通孔180度直针; DSC1: 6p
J31 = J-FPC-6P: Part Name: FPC座; Part Number: J030102870054; ID: 13; DSC6: X05A20L06T(星坤); DSC5: 镀锡; DSC4: H=2mm; DSC3: 下接 翻盖 卧贴; DSC1: 6P
L20 = L-IND: Part Name: 功率电感; Manufacture: 宗成¦长江微电¦顺络; DSC1: ±20%; DSC2: Isat=1.6A; DSC3: Irms=1.25A; DSC4: 260mΩ; DSC5: 2.5*2.0*1.2mm; DSC6: WPN252012H4R7MT(顺络); DSC7: FHD252012S-4R7MT(长江微电); DSC8: ZCRH252012-4.7uH-M(宗成); ID: 54
Q6 = P-MOS: Part Number: C030202190001; Manufacture: 长电; ERP Number: 1010800001; DSC1: Vds=-30V; DSC2: Id=-4.2A; DSC3: Vgs(th)=1.3V; DSC4: Vgs=±12V; DSC5: pd=350mW; ID: 1
Q7 = N-MOS-Q_Dup1: as Q3 on sheet P10
Q8 = N-MOS-Q_Dup1: Part Number: C030202190004; Part Name: N-MOS; Manufacture: 先科; ERP Number: 1010800011; DSC1: Vds=30V; DSC2: Id=100mA; DSC3: Vgs(th)=1.5V; DSC4: Vgs=±20V; DSC5: pd=150mW
R110 R113-R116 = R-0402_Dup4: as R91 on sheet P09
R111 = R-0402_Dup4: Part Name: 贴片电阻; Part Number: C011002080311; ERP Number: 1010200170; DSC1: ±5%; DSC2: 1/16W; ID: 311
R112 = R-0402_Dup4: as R92 on sheet P09
R117 = R-0402_Dup4: as R30 on sheet P07
R118 R134 = R-0402_Dup4: as R99 on sheet P09
R119 = R-0603_Dup1: as R101 on sheet P09
R120 = R-0603_Dup1: as R102 on sheet P09
R121 = R-0402_Dup4: as R58 on sheet P07
R122 = RN_0402X4: Part Number: C010302090001; Part Name: 贴片排阻; DSC2: 1/16W; DSC1: ±5%; ID: 1
R123 = RN_0402X4: Part Name: 贴片排阻; Part Number: C010302090001; ID: 1; DSC1: ±5%; DSC2: 1/16W
R126 R127 = R-0402_Dup4: as R34 on sheet P07
R132 R133 R136 = R-0402_Dup4: as R27 on sheet P07
R135 R138 R409 = R-0402_Dup4: as R81 on sheet P08
R137 = R-0402_Dup4: as R89 on sheet P08
R408 = R-0402_Dup4: as R31 on sheet P07
R417 = R-0402_Dup4: as R32 on sheet P07
U13 = U-SY7201A_2: Part Name: DCDC; Part Number: C070202410024; Manufacture: 矽力杰; ERP Number: 1010100053; DSC1: Vi=2.5-30V; DSC3: Io=2A; DSC4: Vfb=200mV; DSC5: 0.9; DSC6: 1MHz; DSC7: Boost LED驱动; Solder: 量产; ID: 24
U14 = U-74LVC1G125GW-125: Part Name: 逻辑缓冲器; Part Number: C080302460001; Manufacture: Nexperia(安世); ERP Number: 1010100128; DSC1: 1位 高速缓冲 三态输出 VCC=1.65V-5.5V; DSC2: SOT-353; DSC3: -55℃~+125℃; ID: 5

## Sheet P12.SchDoc
size 420 x 297 mm
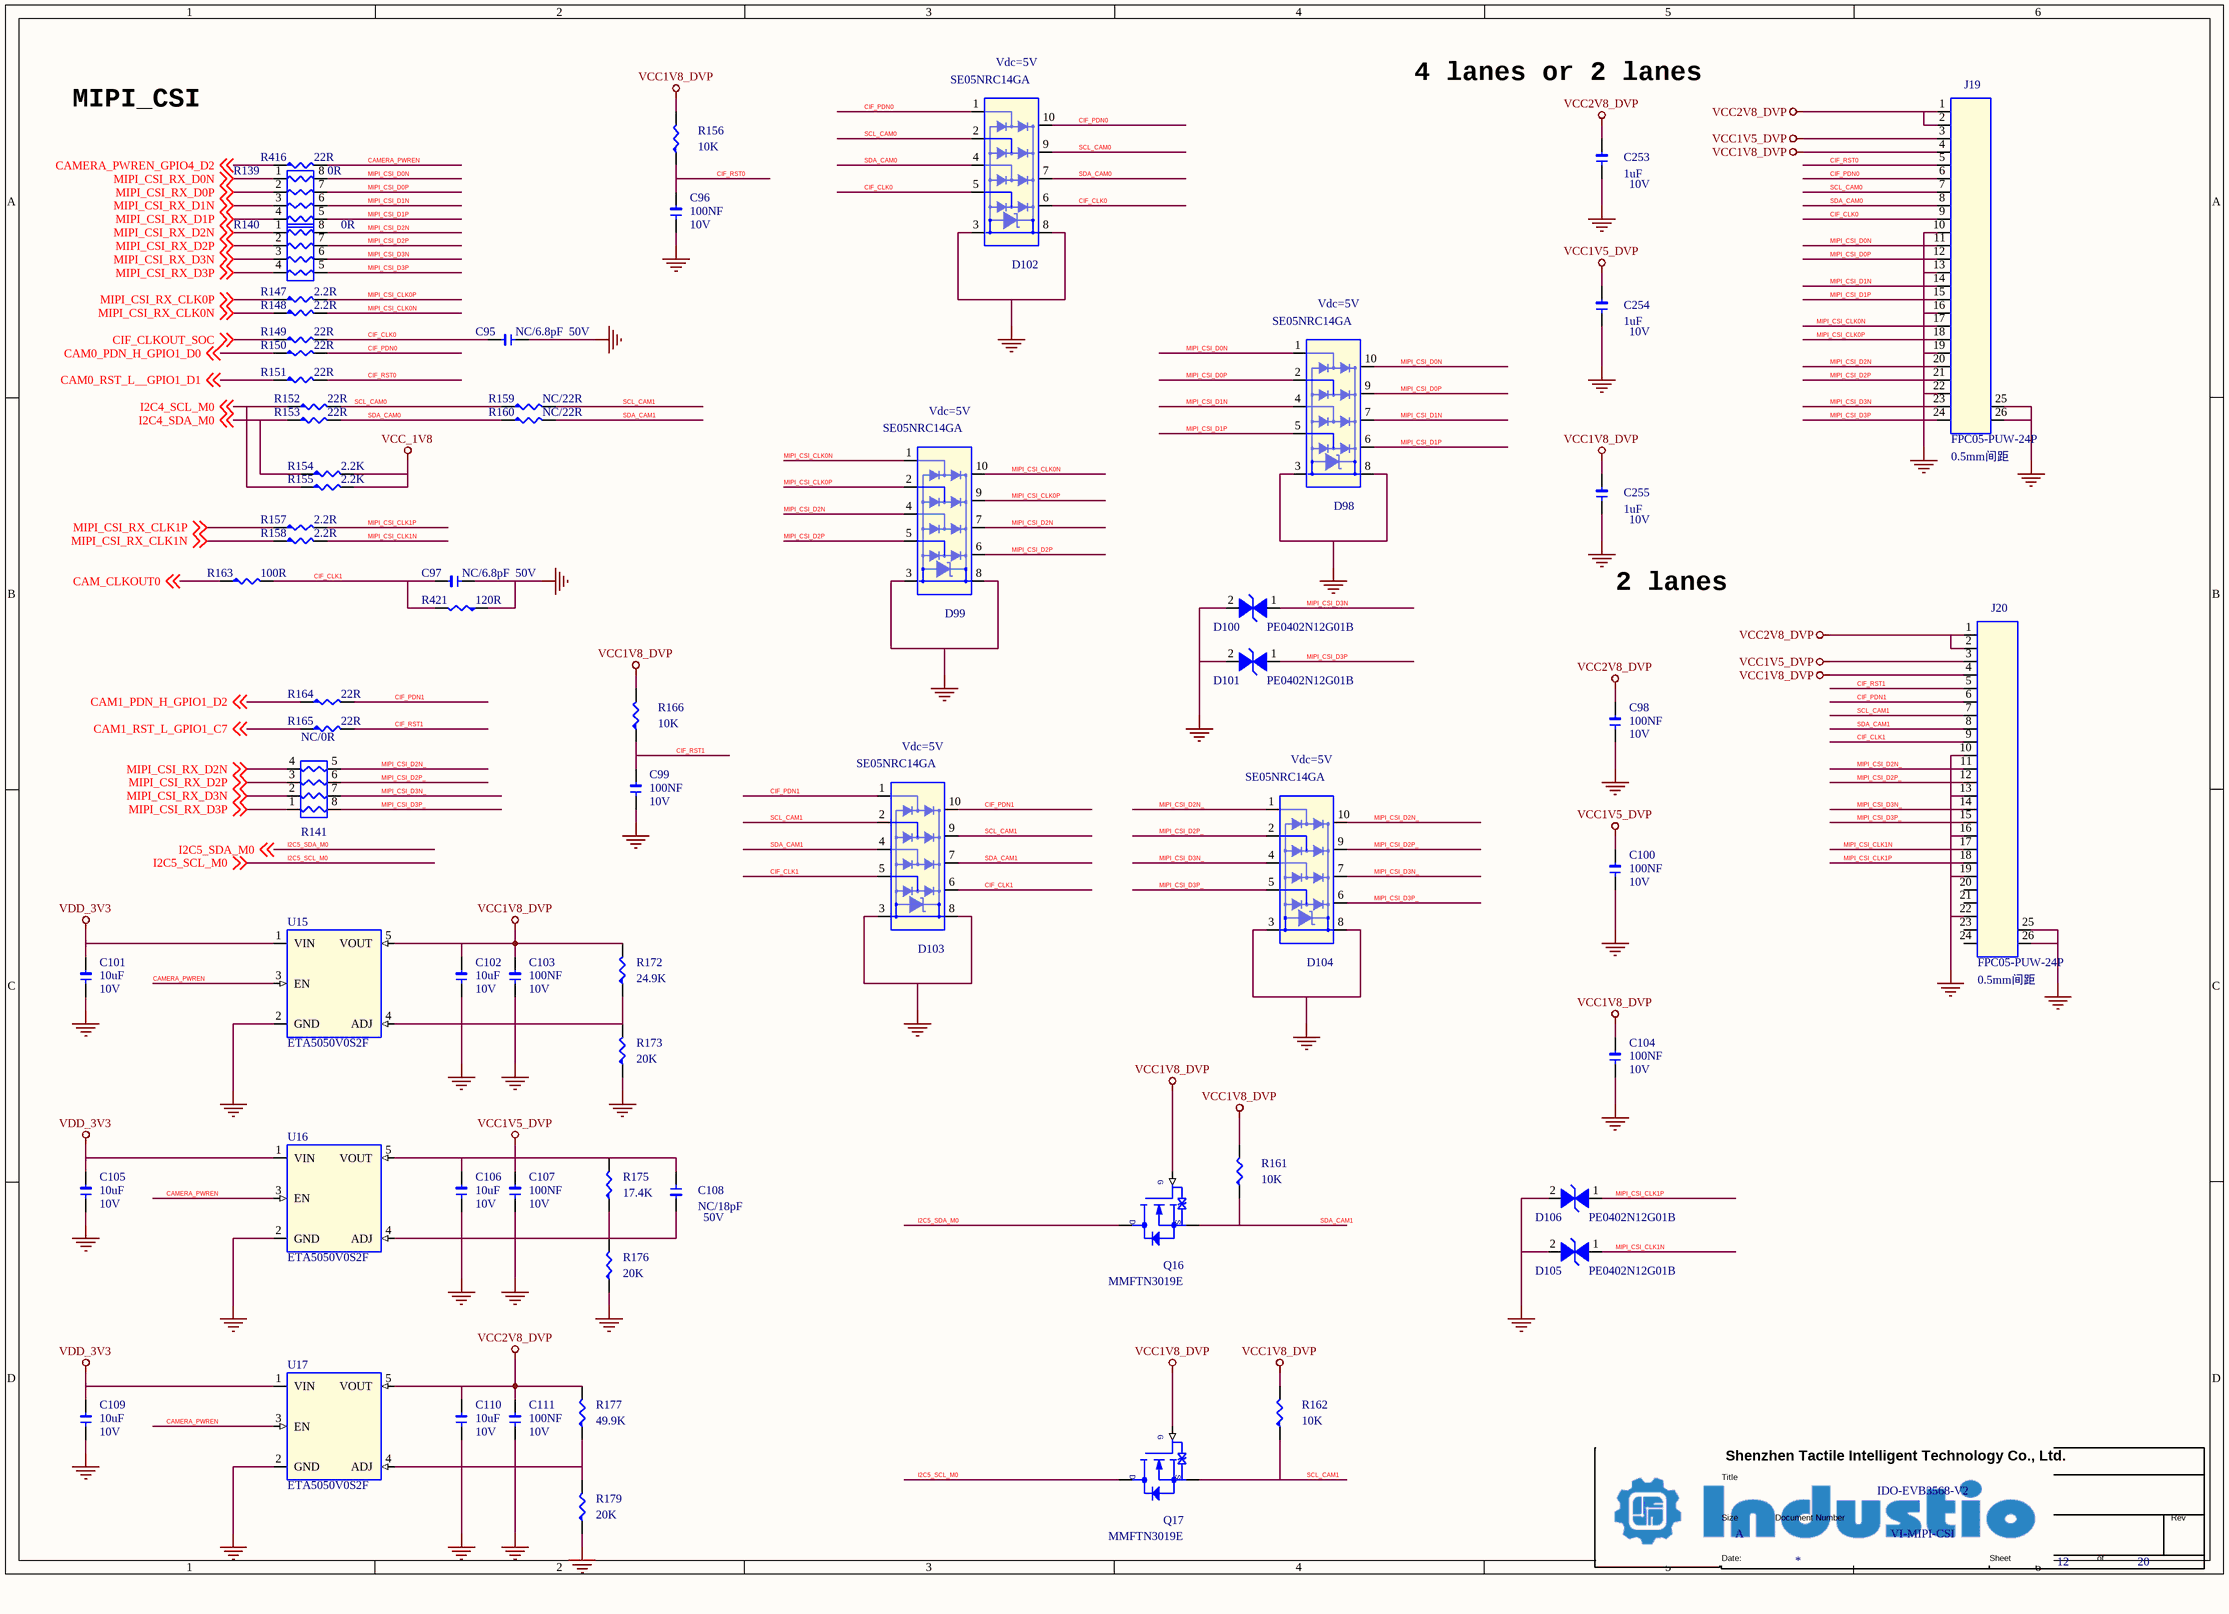
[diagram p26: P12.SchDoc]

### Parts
(Parts that share a designator on the sheet are numbered #1, #2 ... from top to bottom, then left to right.)
*#11  Doc: VI-MIPI-CSI  Title: IDO-EVB3568-V2  Page Size: A  Page Number: 12  Page Count: 20  (hidden comment: TitleBlock1)  (graphical)
C95  NC/6.8pF  DSC2: 50V  [1206]
C96  100NF  DSC2: 10V  [1206]
C97  NC/6.8pF  DSC2: 50V  [1206]
C98  100NF  DSC2: 10V  [1206]
C99  100NF  DSC2: 10V  [1206]
C100  100NF  DSC2: 10V  [1206]
C101  10uF  DSC2: 10V  [1206]
C102  10uF  DSC2: 10V  [1206]
C103  100NF  DSC2: 10V  [1206]
C104  100NF  DSC2: 10V  [1206]
C105  10uF  DSC2: 10V  [1206]
C106  10uF  DSC2: 10V  [1206]
C107  100NF  DSC2: 10V  [1206]
C108  NC/18pF  DSC2: 50V  [1206]
C109  10uF  DSC2: 10V  [1206]
C110  10uF  DSC2: 10V  [1206]
C111  100NF  DSC2: 10V  [1206]
C253  1uF  DSC2: 10V  [1206]
C254  1uF  DSC2: 10V  [1206]
C255  1uF  DSC2: 10V  [1206]
D98  SE05NRC14GA  DSC2: Vdc=5V  [DFN2510-10L]
D99  SE05NRC14GA  DSC2: Vdc=5V  [DFN2510-10L]
D100  PE0402N12G01B  [V0402]
D101  PE0402N12G01B  [V0402]
D102  SE05NRC14GA  DSC2: Vdc=5V  [DFN2510-10L]
D103  SE05NRC14GA  DSC2: Vdc=5V  [DFN2510-10L]
D104  SE05NRC14GA  DSC2: Vdc=5V  [DFN2510-10L]
D105  PE0402N12G01B  [V0402]
D106  PE0402N12G01B  [V0402]
J19  FPC05-PUW-24P  DSC2: 0.5mm间距  [FPC05-24P]
J20  FPC05-PUW-24P  DSC2: 0.5mm间距  [FPC05-24P]
Q16  MMFTN3019E  [SOT523]
Q17  MMFTN3019E  [SOT523]
R139  0R  [RN_0402X4]
R140  0R  [RN_0402X4]
R141  NC/0R  [RN_0402X4]
R147  2.2R  [R0402]
R148  2.2R  [R0402]
R149  22R  [R0402]
R150  22R  [R0402]
R151  22R  [R0402]
R152  22R  [R0402]
R153  22R  [R0402]
R154  2.2K  [R0402]
R155  2.2K  [R0402]
R156  10K  [R0402]
R157  2.2R  [R0402]
R158  2.2R  [R0402]
R159  NC/22R  [R0402]
R160  NC/22R  [R0402]
R161  10K  [R0402]
R162  10K  [R0402]
R163  100R  [R0402]
R164  22R  [R0402]
R165  22R  [R0402]
R166  10K  [R0402]
R172  24.9K  [R0402]
R173  20K  [R0402]
R175  17.4K  [R0402]
R176  20K  [R0402]
R177  49.9K  [R0402]
R179  20K  [R0402]
R416  22R  [R0402]
R421  120R  [R0402]
U15  ETA5050V0S2F  [SOT23-5]
U16  ETA5050V0S2F  [SOT23-5]
U17  ETA5050V0S2F  [SOT23-5]

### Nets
GND: C95.1 C96.1 C97.1 C98.1 C99.1 C100.1 C101.1 C102.1 C103.1 C104.1 C105.1 C106.1 C107.1 C109.1 C110.1 C111.1 C253.1 C254.1 C255.1 D98.3 D98.8 D99.3 D99.8 D100.2(I/O1) D101.2(I/O1) D102.3 D102.8 D103.3 D103.8 D104.3 D104.8 D105.2(I/O1) D106.2(I/O1) J19.10 J19.13 J19.16 J19.19 J19.22 J19.25 J19.26 J20.10 J20.13 J20.16 J20.19 J20.22 J20.25 J20.26 R173.1 R176.1 R179.1 R421.1 U15.2(GND) U16.2(GND) U17.2(GND)  [project net EDP_TX_AUXP_]
VCC1V5_DVP: C100.2 C106.2 C107.2 C108.1 C254.2 J19.3 J20.3 R175.2 U16.5(VOUT)
VCC1V8_DVP: C102.2 C103.2 C104.2 C255.2 J19.4 J20.4 Q16.1(GATE) Q17.1(GATE) R156.2 R161.2 R162.2 R166.2 R172.2 U15.5(VOUT)
VCC2V8_DVP: C98.2 C110.2 C111.2 C253.2 J19.1 J19.2 J20.1 J20.2 R177.2 U17.5(VOUT)
VCC_1V8: R154.2 R155.2
VDD_3V3: C101.2 C105.2 C109.2 U15.1(VIN) U16.1(VIN) U17.1(VIN)
CAM0_PDN_H_GPIO1_D0: R150.1 ; off-sheet CAM0_PDN_H_GPIO1_D0
CAM0_RST_L__GPIO1_D1: R151.1 ; off-sheet CAM0_RST_L__GPIO1_D1
CAM1_PDN_H_GPIO1_D2: R164.1 ; off-sheet CAM1_PDN_H_GPIO1_D2
CAM1_RST_L_GPIO1_C7: R165.1 ; off-sheet CAM1_RST_L_GPIO1_C7
CAM_CLKOUT0: R163.1 ; off-sheet CAM_CLKOUT0
CAMERA_PWREN: R416.2 U15.3(EN) U16.3(EN) U17.3(EN)
CAMERA_PWREN_GPIO4_D2: R416.1 ; off-sheet CAMERA_PWREN_GPIO4_D2
CIF_CLK0: C95.2 D102.5 D102.6 J19.9 R149.2
CIF_CLK1: C97.2 D103.5 D103.6 J20.9 R163.2 R421.2
CIF_CLKOUT_SOC: R149.1 ; off-sheet CIF_CLKOUT_SOC
CIF_PDN0: D102.1 D102.10 J19.6 R150.2
CIF_PDN1: D103.1 D103.10 J20.6 R164.2
CIF_RST0: C96.2 J19.5 R151.2 R156.1
CIF_RST1: C99.2 J20.5 R165.2 R166.1
I2C4_SCL_M0: R152.1 R155.1 ; off-sheet I2C4_SCL_M0
I2C4_SDA_M0: R153.1 R154.1 ; off-sheet I2C4_SDA_M0
I2C5_SCL_M0: Q17.3(DRAIN) ; off-sheet I2C5_SCL_M0
I2C5_SDA_M0: Q16.3(DRAIN) ; off-sheet I2C5_SDA_M0
MIPI_CSI_CLK0N: D99.1 D99.10 J19.17 R148.2
MIPI_CSI_CLK0P: D99.2 D99.9 J19.18 R147.2
MIPI_CSI_CLK1N: D105.1(I/O2) J20.17 R158.2
MIPI_CSI_CLK1P: D106.1(I/O2) J20.18 R157.2
MIPI_CSI_D0N: D98.1 D98.10 J19.11 R139.8
MIPI_CSI_D0P: D98.2 D98.9 J19.12 R139.7
MIPI_CSI_D1N: D98.4 D98.7 J19.14 R139.6
MIPI_CSI_D1P: D98.5 D98.6 J19.15 R139.5
MIPI_CSI_D2N: D99.4 D99.7 J19.20 R140.8
MIPI_CSI_D2N_: D104.1 D104.10 J20.11 R141.5
MIPI_CSI_D2P: D99.5 D99.6 J19.21 R140.7
MIPI_CSI_D2P_: D104.2 D104.9 J20.12 R141.6
MIPI_CSI_D3N: D100.1(I/O2) J19.23 R140.6
MIPI_CSI_D3N_: D104.4 D104.7 J20.14 R141.7
MIPI_CSI_D3P: D101.1(I/O2) J19.24 R140.5
MIPI_CSI_D3P_: D104.5 D104.6 J20.15 R141.8
MIPI_CSI_RX_CLK0N: R148.1 ; off-sheet MIPI_CSI_RX_CLK0N
MIPI_CSI_RX_CLK0P: R147.1 ; off-sheet MIPI_CSI_RX_CLK0P
MIPI_CSI_RX_CLK1N: R158.1 ; off-sheet MIPI_CSI_RX_CLK1N
MIPI_CSI_RX_CLK1P: R157.1 ; off-sheet MIPI_CSI_RX_CLK1P
MIPI_CSI_RX_D0N: R139.1 ; off-sheet MIPI_CSI_RX_D0N
MIPI_CSI_RX_D0P: R139.2 ; off-sheet MIPI_CSI_RX_D0P
MIPI_CSI_RX_D1N: R139.3 ; off-sheet MIPI_CSI_RX_D1N
MIPI_CSI_RX_D1P: R139.4 ; off-sheet MIPI_CSI_RX_D1P
MIPI_CSI_RX_D2N: R140.1 R141.4 ; off-sheet MIPI_CSI_RX_D2N
MIPI_CSI_RX_D2P: R140.2 R141.3 ; off-sheet MIPI_CSI_RX_D2P
MIPI_CSI_RX_D3N: R140.3 R141.2 ; off-sheet MIPI_CSI_RX_D3N
MIPI_CSI_RX_D3P: R140.4 R141.1 ; off-sheet MIPI_CSI_RX_D3P
SCL_CAM0: D102.2 D102.9 J19.7 R152.2 R159.1
SCL_CAM1: D103.2 D103.9 J20.7 Q17.2(SOURCE) R159.2 R162.1
SDA_CAM0: D102.4 D102.7 J19.8 R153.2 R160.1
SDA_CAM1: D103.4 D103.7 J20.8 Q16.2(SOURCE) R160.2 R161.1
NetC108_2: C108.2 R175.1 R176.2 U16.4(ADJ)
NetR172_1: R172.1 R173.2 U15.4(ADJ)
NetR177_1: R177.1 R179.2 U17.4(ADJ)

Not connected (* = marked no-connect by the designer): J20 20 21 23 24

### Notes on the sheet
- MIPI_CSI
- 4 lanes or 2 lanes
- 2 lanes

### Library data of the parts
C95 = C-0402_Dup2: Manufacture: 三星¦国巨¦村田; Part Name: 贴片电容; Part Number: C020102120018; PCB Footprint: C0402; ID: 18; DSC3: C0G; DSC1: ±0.25PF; ERP Number: 1010200056
C96 C104 = C-0402_Dup2: as C88 on sheet P11
C97 = C-0402_Dup2: Part Number: C020102120018; Part Name: 贴片电容; Manufacture: 三星¦国巨¦村田; ERP Number: 1010200056; DSC1: ±0.25PF; DSC3: C0G; ID: 18; PCB Footprint: C0402
C98 C100 = C-0402_Dup2: as C82 on sheet P09
C99 C103 C111 = C-0402_Dup2: as C55 on sheet P07
C101 C105 C109 = C-0603_Dup2: as C50 on sheet P07
C102 C106 C110 = C-0603_Dup2: as C44 on sheet P07
C107 = C-0402_Dup2: as C39 on sheet P07
C108 = C-0402_Dup2: Manufacture: 三星¦国巨¦村田; Part Name: 贴片电容; Part Number: C020102120027; PCB Footprint: C0402; ID: 27; DSC3: C0G; DSC1: ±5%; ERP Number: 1010200091
C253-C255 = C-0402_Dup1: as C71 on sheet P08
D98 D104 = DI-ESD-SE05NRC14GA: as D14 on sheet P07
D99 D102 D103 = DI-ESD-SE05NRC14GA: as D17 on sheet P07
D100 D106 = DI-ESD: as D10 on sheet P07
D101 D105 = DI-ESD: as D7-D9 on sheet P07
J19 J20 = J-FPC-24P: Part Name: FPC座; Part Number: J030102870021; ID: 34; DSC6: X05B20U24T(星坤); DSC5: 镀锡; DSC4: H=2mm; DSC3: 上接 抽拉式 卧贴; DSC1: 24P
Q16 = N-MOS-Q_Dup1: as Q1 on sheet P07
Q17 = N-MOS-Q_Dup1: as Q3 on sheet P10
R139 = RN_0402X4: as R122 on sheet P11
R140 R141 = RN_0402X4: as R123 on sheet P11
R147 R157 = R-0402_Dup4: as R29 on sheet P07
R148 R158 = R-0402_Dup4: as R34 on sheet P07
R149-R152 R164 R165 R416 = R-0402_Dup4: as R91 on sheet P09
R153 R159 R160 = R-0402_Dup4: as R32 on sheet P07
R154 = R-0402_Dup4: as R111 on sheet P11
R155 = R-0402_Dup4: as R92 on sheet P09
R156 R161 R162 R166 = R-0402_Dup4: as R27 on sheet P07
R163 = R-0402_Dup4: Part Number: C011002080279; Part Name: 贴片电阻; ID: 279; DSC2: 1/16W; DSC1: ±5%; ERP Number: 1010200160
R172 = R-0402_Dup4: Part Number: C011002080900; Part Name: 贴片电阻; ID: 900; DSC2: 1/16W; DSC1: ±1%; ERP Number: 1010200327
R173 R176 R179 = R-0402_Dup4: Part Name: 贴片电阻; Part Number: C011002080889; ERP Number: 1010200333; DSC1: ±1%; DSC2: 1/16W; ID: 889
R175 = R-0402_Dup4: Part Number: C011002080882; Part Name: 贴片电阻; ID: 882; DSC2: 1/16W; DSC1: ±1%
R177 = R-0402_Dup4: Part Number: C011002080938; Part Name: 贴片电阻; ID: 938; DSC2: 1/16W; DSC1: ±1%
R421 = R-0402_Dup4: Part Name: 贴片电阻; Part Number: C011002080281; DSC1: ±5%; DSC2: 1/16W; ID: 281
U15-U17 = U-ETA5050: Manufacture: ETA; Part Number: C070111104620; Part Name: LDO; Solder: 推荐; ID: 28; DSC5: Iq=40uA; DSC3: Io=500mA; DSC2: Vo=adj; DSC1: Vi=2.5-5.5V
